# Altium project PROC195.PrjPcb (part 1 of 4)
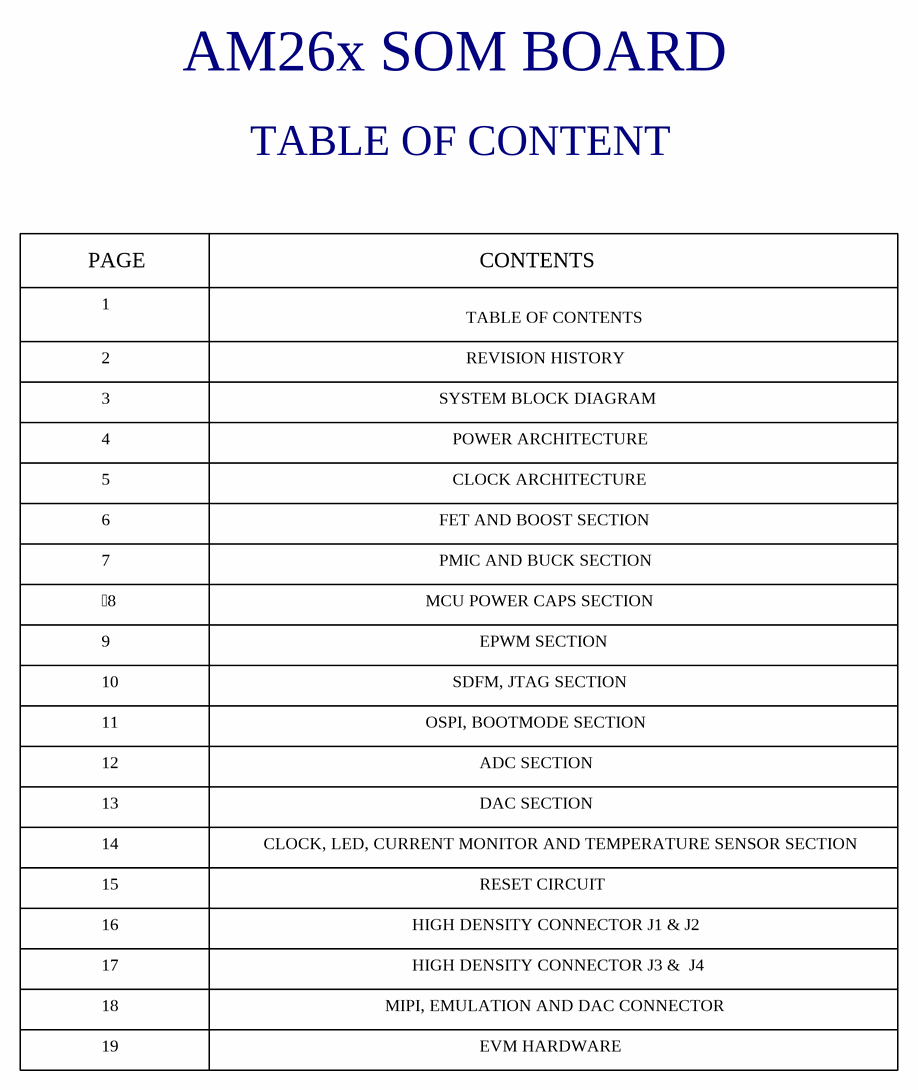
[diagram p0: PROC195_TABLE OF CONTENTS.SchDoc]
TID: N/A; SCH_REV: E1; PRJ_Title: AM26x_SOM; PRJ_Number: PROC195; PRJ_Customer: Public Release; PCB_Rev: E1; EVM_orderable: AM261-SOM-EVM; DrawnBy: Texas Instruments
20 sheets, 559 parts. Net scope: global (net labels, ports and power ports of the same name join across sheets).
Board file: PROC195E1_PCB.PcbDoc
Sheets:
  PROC195_TABLE OF CONTENTS.SchDoc
  PROC195_REVISION_HISTORY.SchDoc
  PROC195_SYSTEM_BLOCK_DIAGRAM.SchDoc
  PROC195_POWER_ARCHITECTURE.SchDoc
  PROC195_CLOCK_ARCHITECTURE.SchDoc
  PROC195_GPIO_TABLE.SchDoc
  PROC195__FET_BOOST_REG.SchDoc
  PROC195_PMIC_BUCK.SchDoc
  PROC195_MCU_POWER_CAPS.SchDoc
  PROC195_EPWM.SchDoc
  PROC195_SDFM, JTAG.SchDoc
  PROC195_OSPI_BOOTMODE.SchDoc
  PROC195_ADC.SchDoc
  PROC195_DAC.SchDoc
  PROC195_CLK_LED_CURRENT_MON_TEMP_CONN.SchDoc
  PROC195_RESET_CIRCUIT.SchDoc
  PROC195_High_density_conn_1_2.SchDoc
  PROC195_High_density_conn3_4.SchDoc
  PROC195_MIPI_Emulation_conn.SchDoc
  PROC195_EVM_Hardware.SchDoc

## Sheet PROC195_TABLE OF CONTENTS.SchDoc
size 431 x 279 mm; Date: Not shown in title block; ApprovedBy: Not shown in title block; CheckedBy: Not shown in title block; Author: Not shown in title block; CompanyName: Not shown in title block; Engineer: Not shown in title block; Organization: Not shown in title block; Address1: Not shown in title block; Address2: Not shown in title block; Address3: Not shown in title block; Address4: Not shown in title block; DocumentNumber: 1; Revision: Use project parameter SCH_Rev; SheetNumber: 1; SheetTotal: 19; PageSetup: Record=PageOptions¦CenterHorizontal=True¦CenterVertical=True¦PrintScale=1.00¦XCorrection=1.00¦YCorrection=1.00¦PrintKind=0¦BorderSize=5000000¦LeftOffset=0¦BottomOffset=0¦Orientation=2¦PaperLength=1000¦PaperWidth=1000¦Scale=100¦PaperSource=15¦PrintQuality=600¦MediaType=1¦DitherType=10¦PaperKind=Letter¦PrintScaleMode=1

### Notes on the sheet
- AM26x SOM BOARD
- TABLE OF CONTENT
- PAGE
- 1
- TABLE OF CONTENTS
- CONTENTS
- 2
- REVISION HISTORY
- 3
- 4
- SYSTEM BLOCK DIAGRAM
- POWER ARCHITECTURE
- 5
- 6
- FET AND BOOST SECTION
- CLOCK ARCHITECTURE
- 7
- PMIC AND BUCK SECTION
- 8
- 9
- MCU POWER CAPS SECTION
- EPWM SECTION
- 10
- 11
- OSPI, BOOTMODE SECTION
- SDFM, JTAG SECTION
- 12
- ADC SECTION
- 13
- 14
- CLOCK, LED, CURRENT MONITOR AND TEMPERATURE SENSOR SECTION
- DAC SECTION
- 15
- 16
- HIGH DENSITY CONNECTOR J1 & J2
- RESET CIRCUIT
- 17
- HIGH DENSITY CONNECTOR J3 &  J4
- 18
- 19
- MIPI, EMULATION AND DAC CONNECTOR
- EVM HARDWARE

## Sheet PROC195_REVISION_HISTORY.SchDoc
size 431 x 279 mm; Date: Not shown in title block; ApprovedBy: Not shown in title block; CheckedBy: Not shown in title block; Author: Not shown in title block; CompanyName: Not shown in title block; Engineer: Not shown in title block; Organization: Not shown in title block; Address1: Not shown in title block; Address2: Not shown in title block; Address3: Not shown in title block; Address4: Not shown in title block; DocumentNumber: 2; Revision: Use project parameter SCH_Rev; SheetNumber: 2; SheetTotal: 20; PageSetup: Record=PageOptions¦CenterHorizontal=True¦CenterVertical=True¦PrintScale=1.00¦XCorrection=1.00¦YCorrection=1.00¦PrintKind=0¦BorderSize=5000000¦LeftOffset=0¦BottomOffset=0¦Orientation=2¦PaperLength=1000¦PaperWidth=1000¦Scale=100¦PaperSource=15¦PrintQuality=600¦MediaType=1¦DitherType=10¦PaperKind=Letter¦PrintScaleMode=1
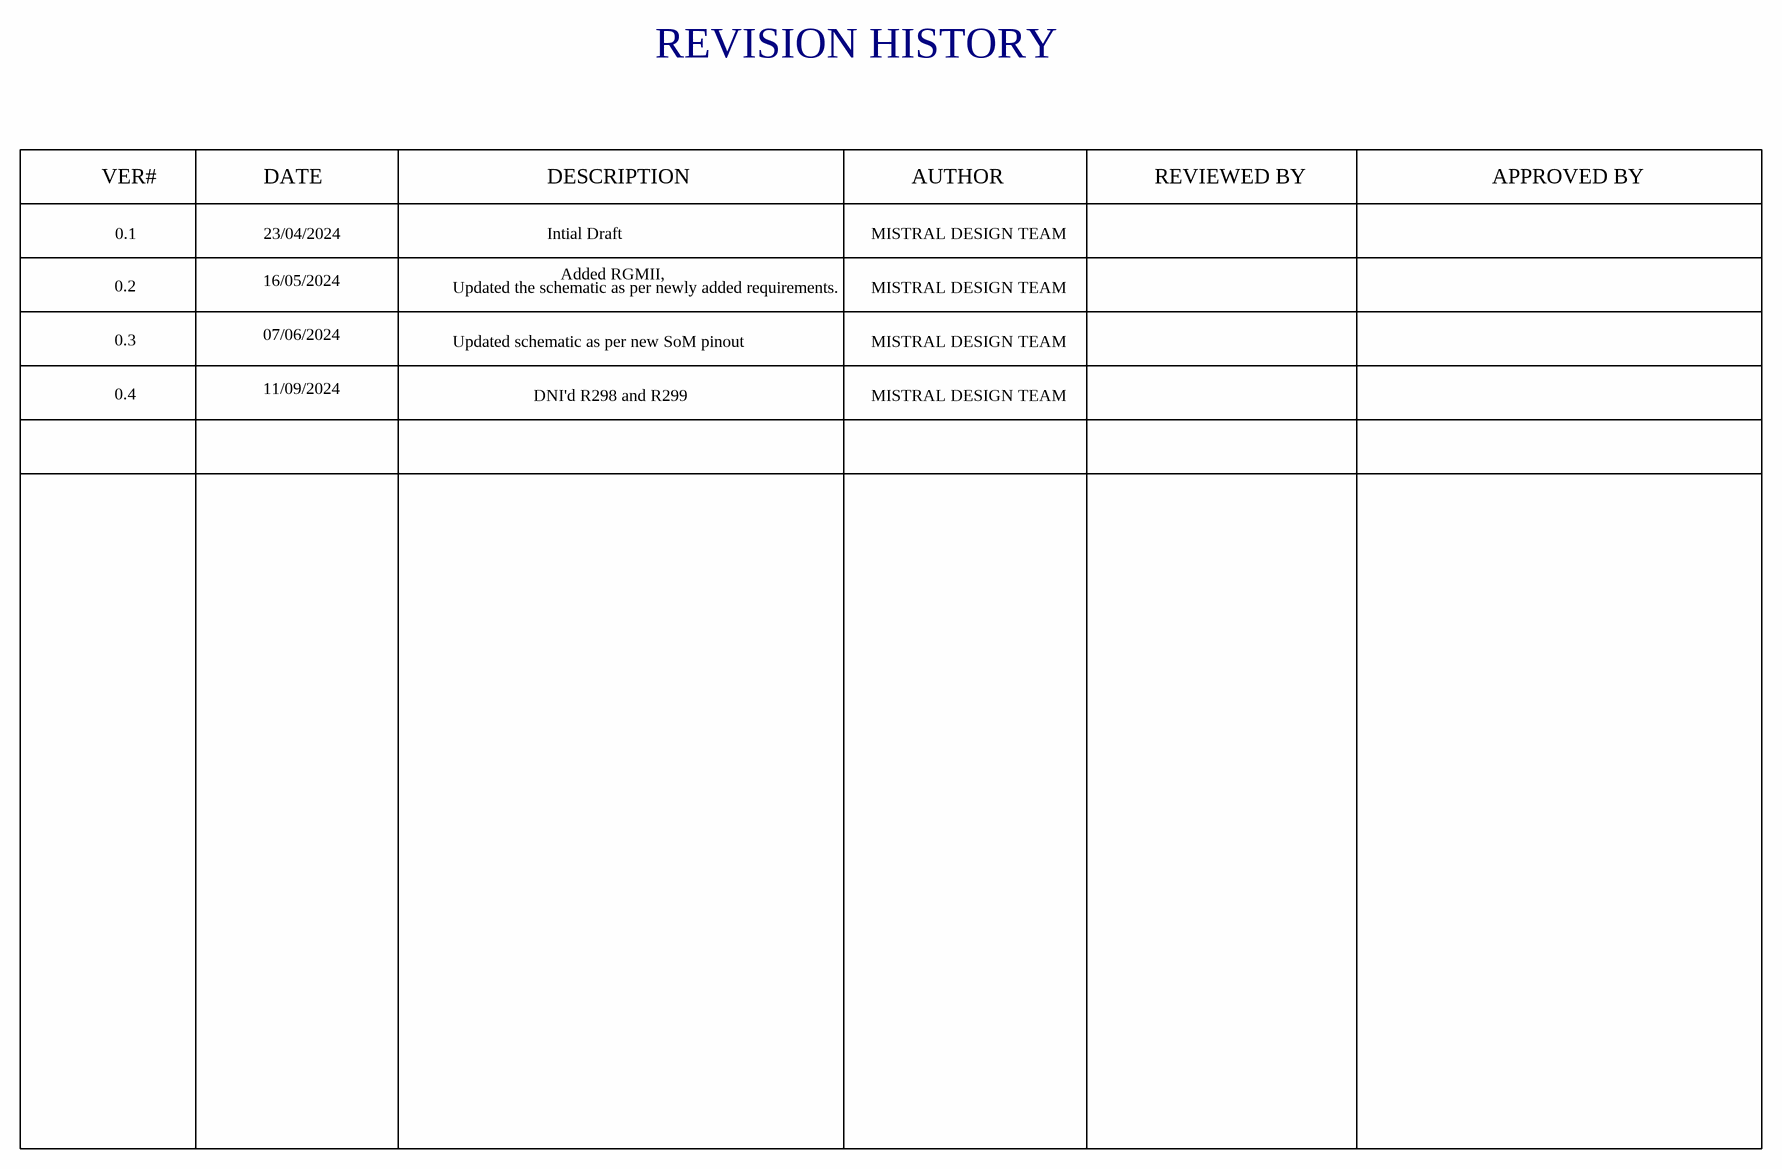
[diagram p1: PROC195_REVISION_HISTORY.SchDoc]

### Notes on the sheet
- REVISION HISTORY
- VER#
- DATE
- DESCRIPTION
- AUTHOR
- REVIEWED BY
- APPROVED BY
- 0.2
- 0.1
- 16/05/2024
- 23/04/2024
- Updated the schematic as per newly added requirements.
- Intial Draft
- Added RGMII,
- MISTRAL DESIGN TEAM
- 0.3
- 07/06/2024
- Updated schematic as per new SoM pinout
- 0.4
- 11/09/2024
- DNI'd R298 and R299

## Sheet PROC195_SYSTEM_BLOCK_DIAGRAM.SchDoc
size 431 x 279 mm; Date: Not shown in title block; ApprovedBy: Not shown in title block; CheckedBy: Not shown in title block; Author: Not shown in title block; CompanyName: Not shown in title block; Engineer: Not shown in title block; Organization: Not shown in title block; Address1: Not shown in title block; Address2: Not shown in title block; Address3: Not shown in title block; Address4: Not shown in title block; DocumentNumber: 3; Revision: Use project parameter SCH_Rev; SheetNumber: 3; SheetTotal: 20; PageSetup: Record=PageOptions¦CenterHorizontal=True¦CenterVertical=True¦PrintScale=1.00¦XCorrection=1.00¦YCorrection=1.00¦PrintKind=0¦BorderSize=5000000¦LeftOffset=0¦BottomOffset=0¦Orientation=2¦PaperLength=1000¦PaperWidth=1000¦Scale=100¦PaperSource=15¦PrintQuality=600¦MediaType=1¦DitherType=10¦PaperKind=Letter¦PrintScaleMode=1
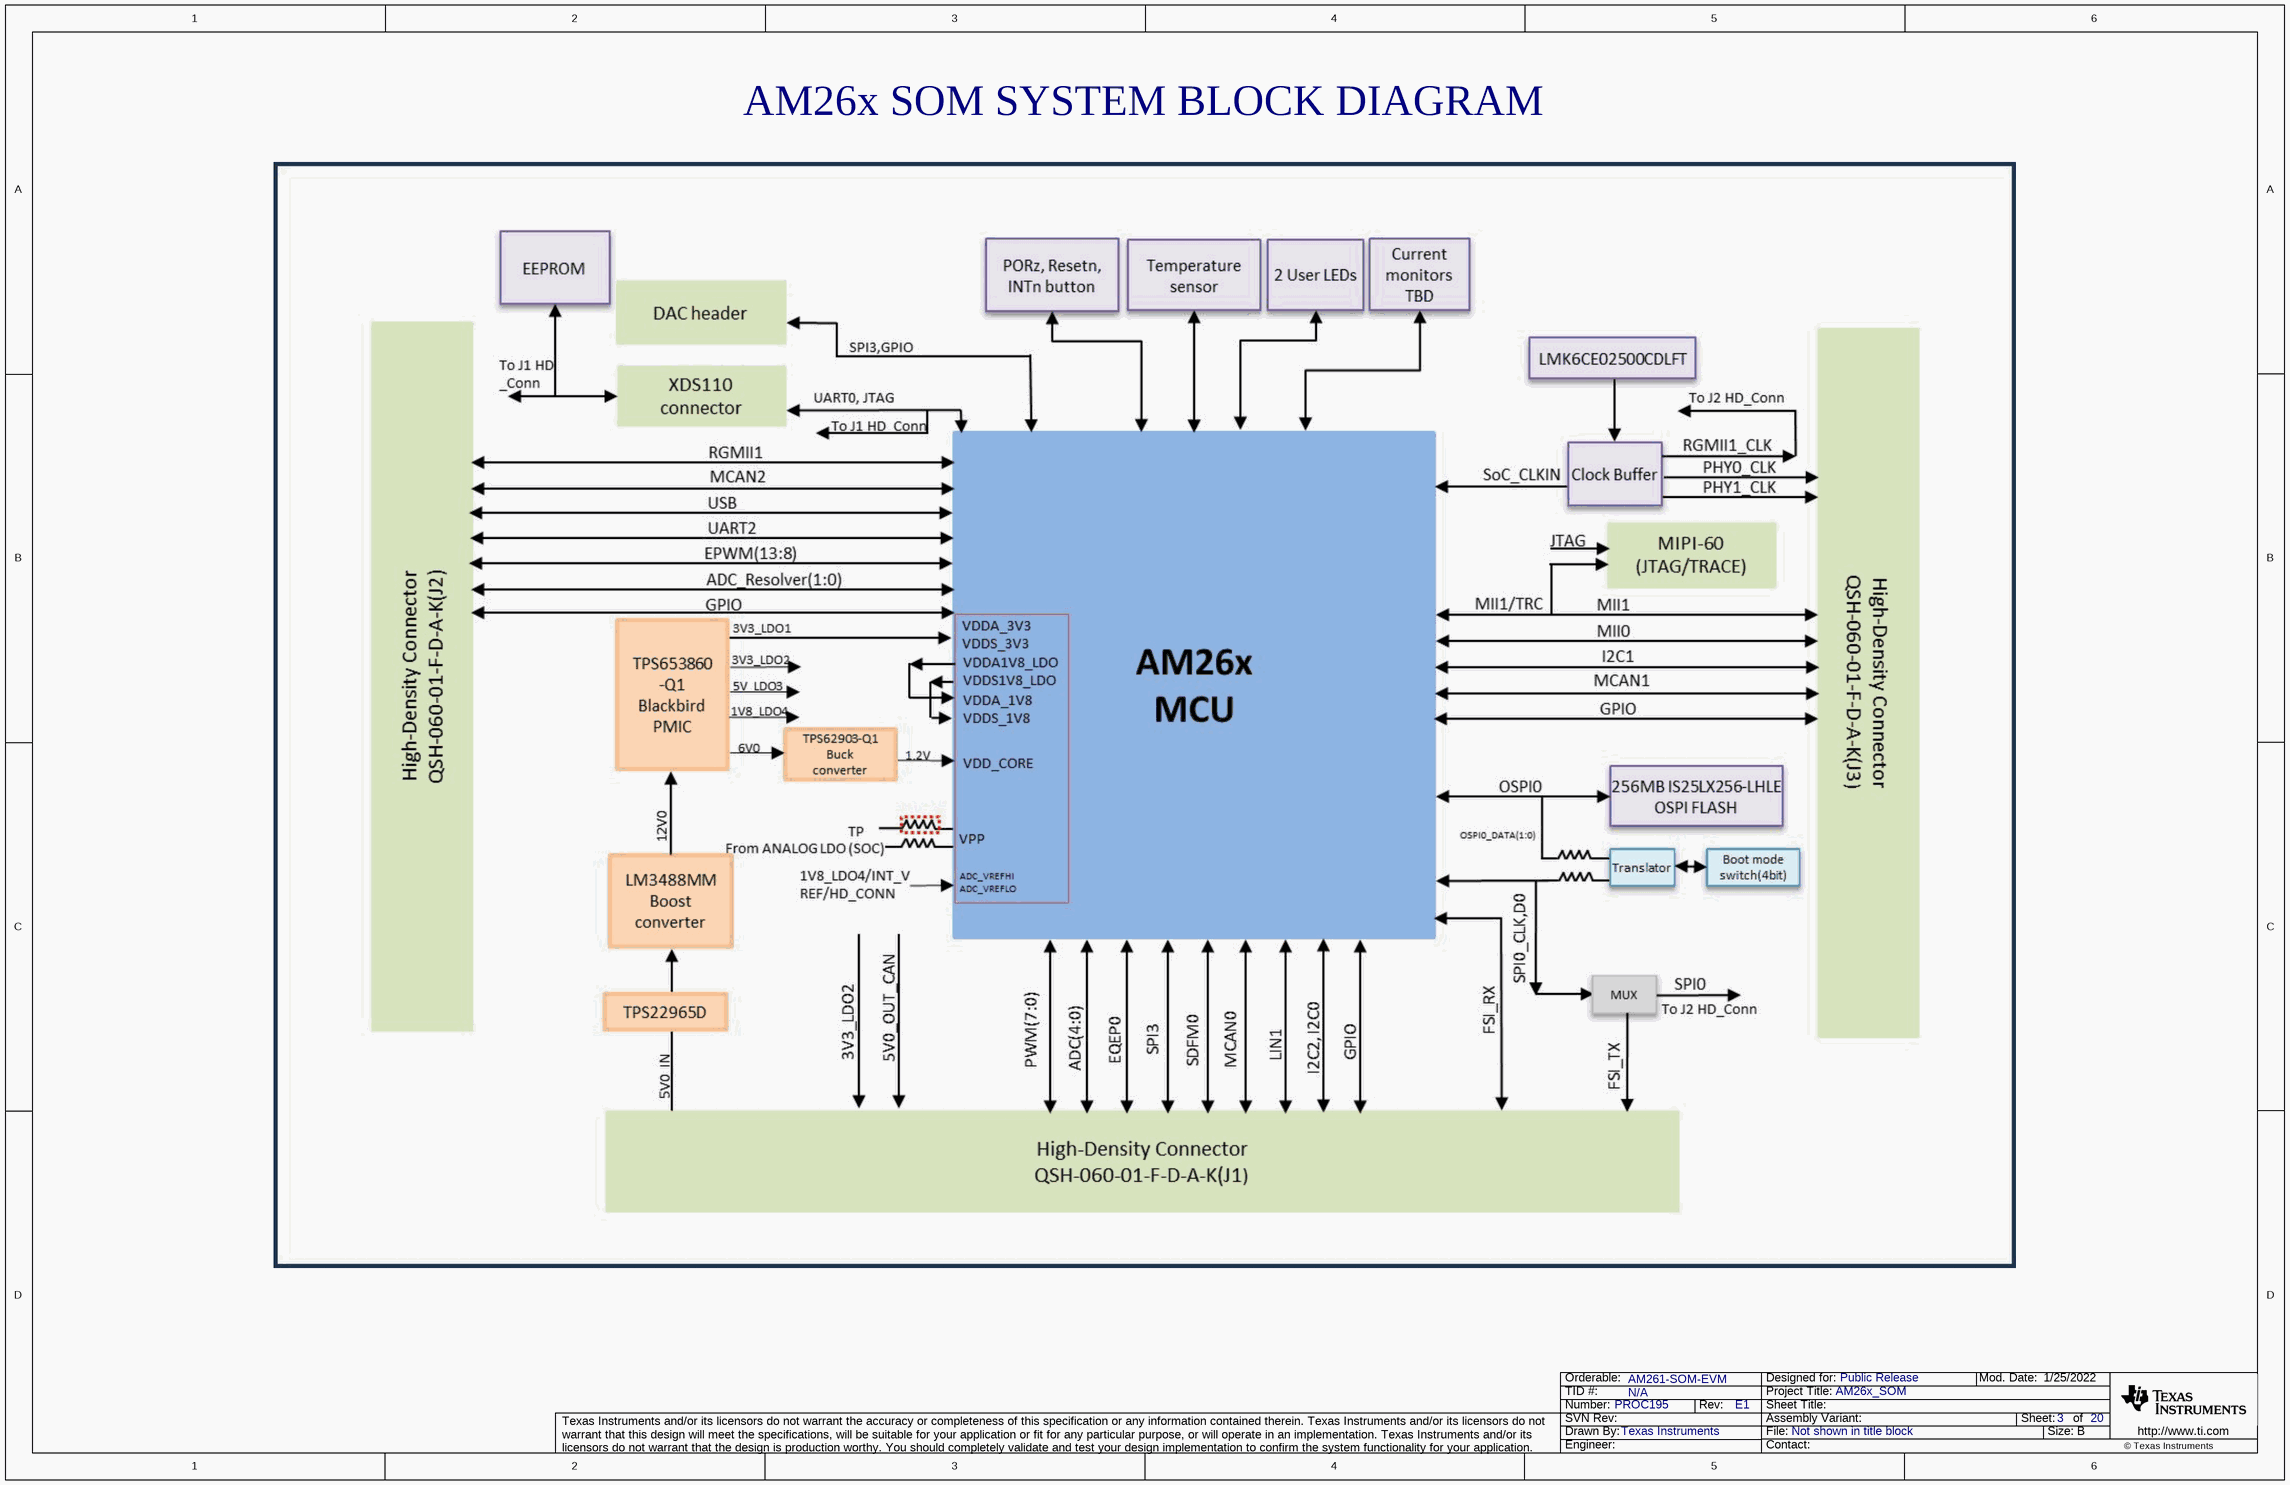
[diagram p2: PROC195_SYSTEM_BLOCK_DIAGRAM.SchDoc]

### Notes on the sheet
- AM26x SOM SYSTEM BLOCK DIAGRAM

## Sheet PROC195_POWER_ARCHITECTURE.SchDoc
size 431 x 279 mm; Date: Not shown in title block; ApprovedBy: Not shown in title block; CheckedBy: Not shown in title block; Author: Not shown in title block; CompanyName: Not shown in title block; Engineer: Not shown in title block; Organization: Not shown in title block; Address1: Not shown in title block; Address2: Not shown in title block; Address3: Not shown in title block; Address4: Not shown in title block; DocumentNumber: 4; Revision: Use project parameter SCH_Rev; SheetNumber: 4; SheetTotal: 19; PageSetup: Record=PageOptions¦CenterHorizontal=True¦CenterVertical=True¦PrintScale=1.00¦XCorrection=1.00¦YCorrection=1.00¦PrintKind=0¦BorderSize=5000000¦LeftOffset=0¦BottomOffset=0¦Orientation=2¦PaperLength=1000¦PaperWidth=1000¦Scale=100¦PaperSource=15¦PrintQuality=600¦MediaType=1¦DitherType=10¦PaperKind=Letter¦PrintScaleMode=1
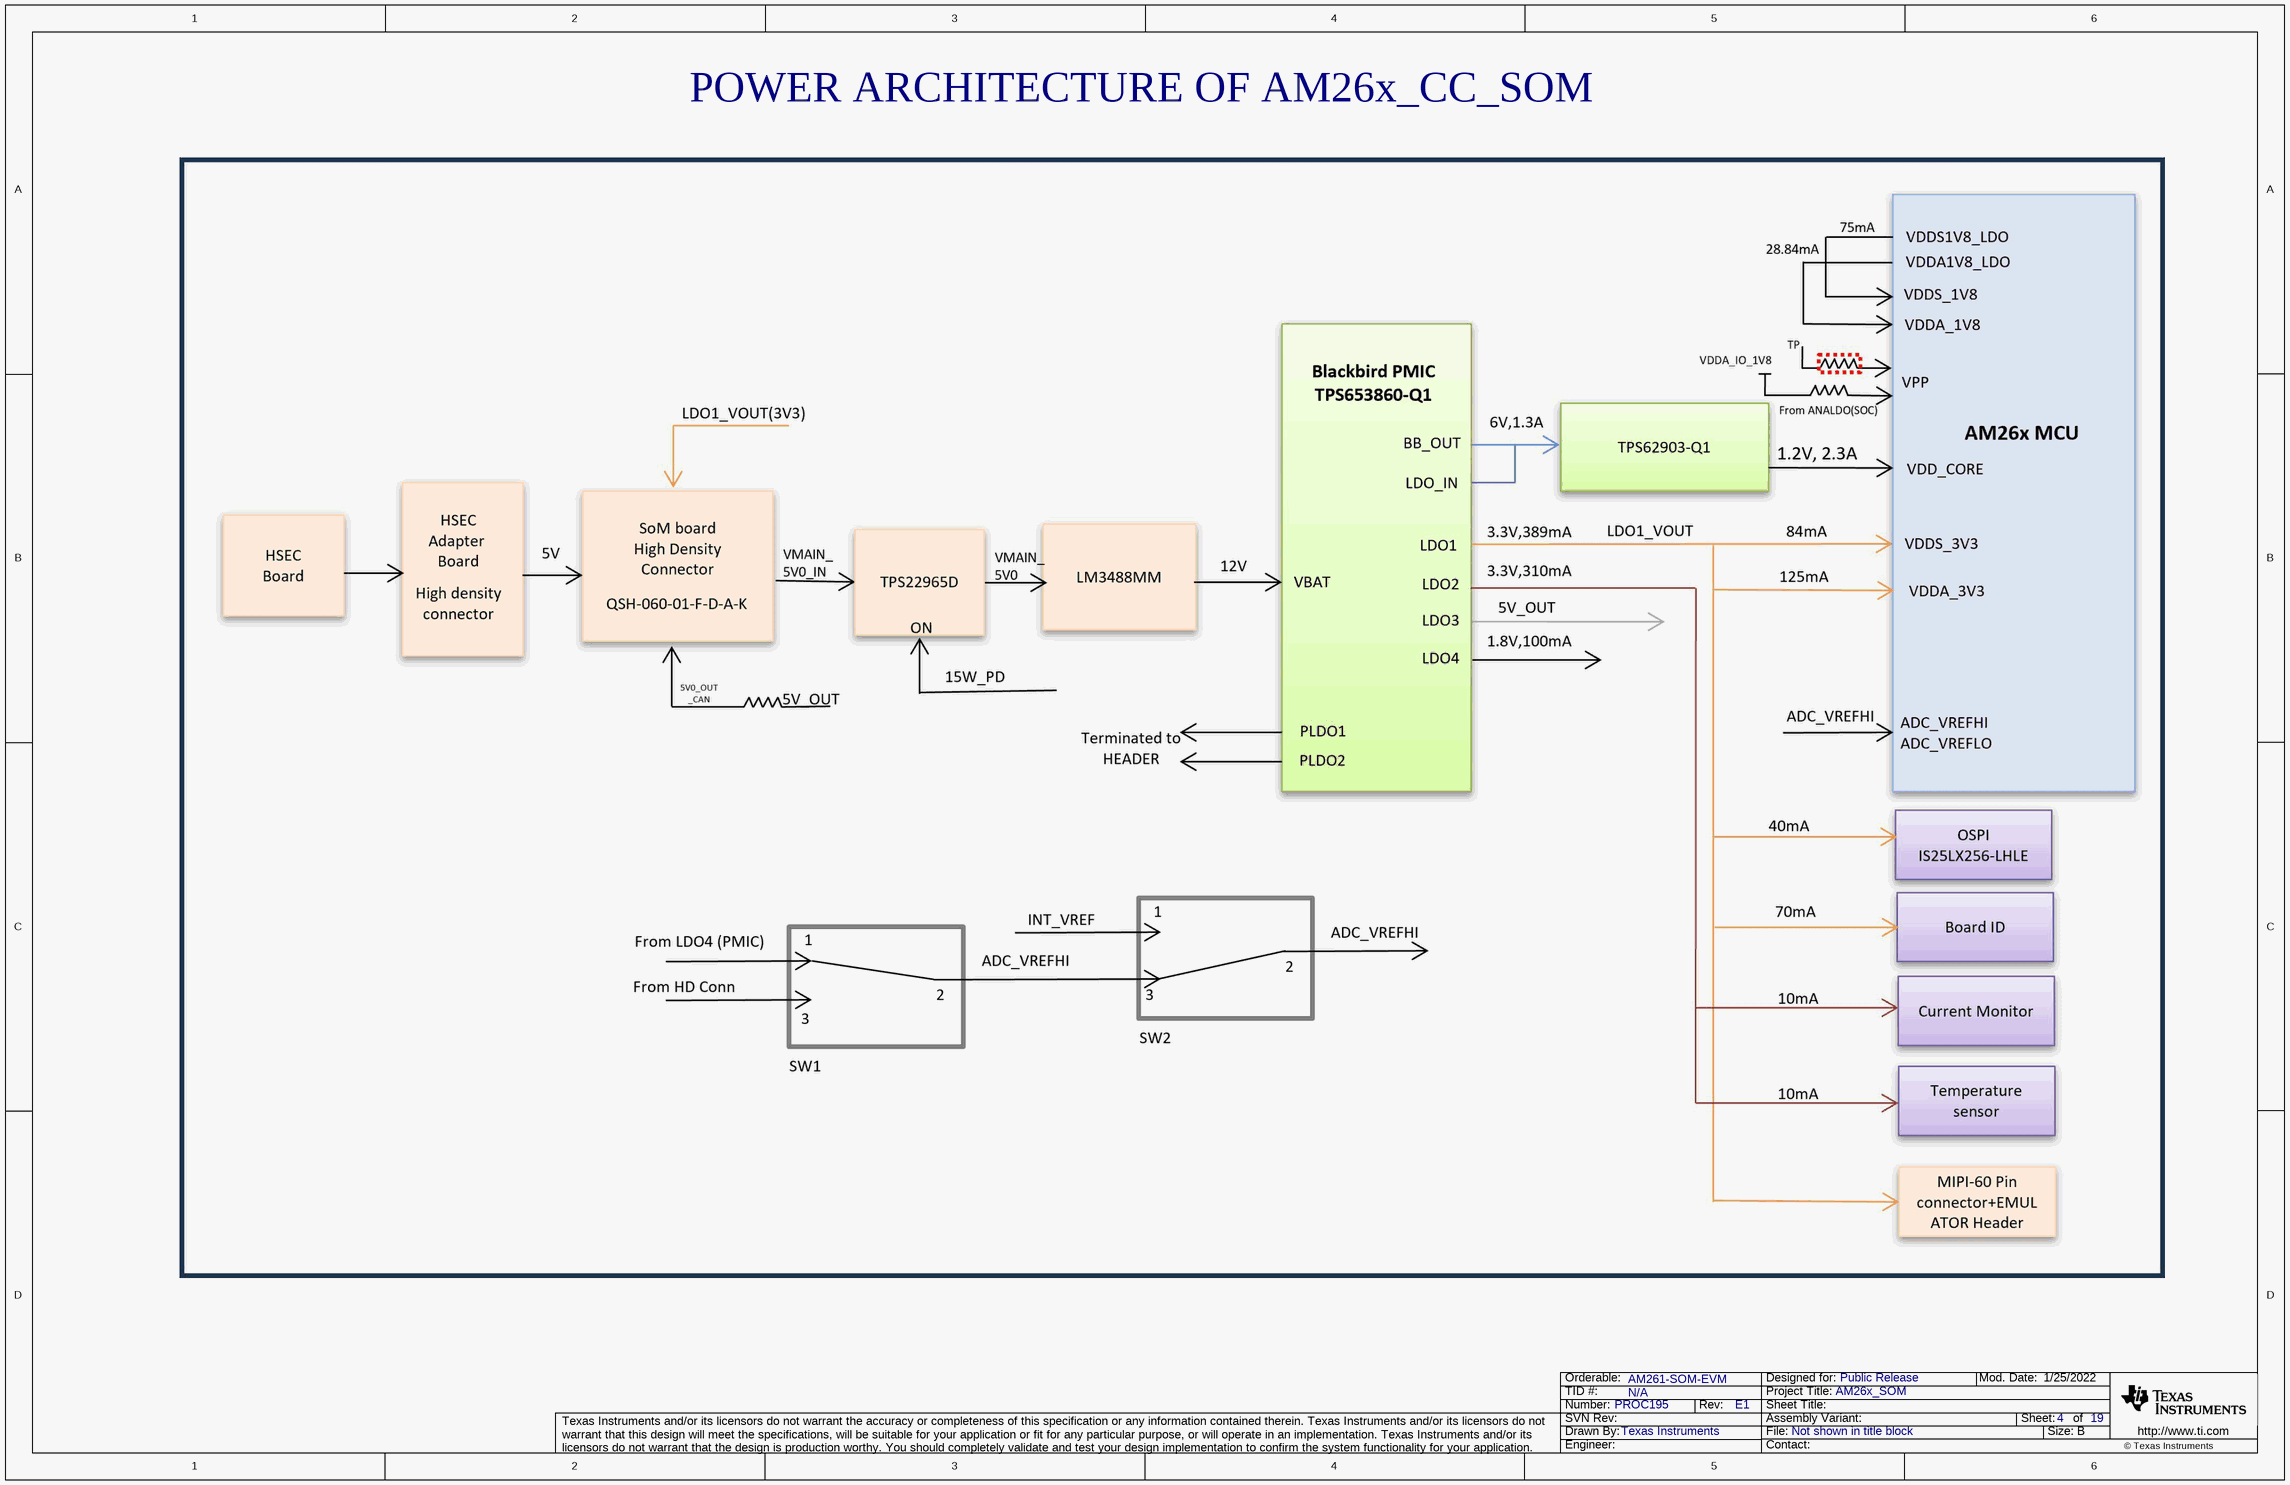
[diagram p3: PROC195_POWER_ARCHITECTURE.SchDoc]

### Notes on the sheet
- POWER ARCHITECTURE OF AM26x_CC_SOM

## Sheet PROC195_CLOCK_ARCHITECTURE.SchDoc
size 431 x 279 mm; Date: Not shown in title block; ApprovedBy: Not shown in title block; CheckedBy: Not shown in title block; Author: Not shown in title block; CompanyName: Not shown in title block; Engineer: Not shown in title block; Organization: Not shown in title block; Address1: Not shown in title block; Address2: Not shown in title block; Address3: Not shown in title block; Address4: Not shown in title block; DocumentNumber: 5; Revision: Use project parameter SCH_Rev; SheetNumber: 5; SheetTotal: 20; PageSetup: Record=PageOptions¦CenterHorizontal=True¦CenterVertical=True¦PrintScale=1.00¦XCorrection=1.00¦YCorrection=1.00¦PrintKind=0¦BorderSize=5000000¦LeftOffset=0¦BottomOffset=0¦Orientation=2¦PaperLength=1000¦PaperWidth=1000¦Scale=100¦PaperSource=15¦PrintQuality=600¦MediaType=1¦DitherType=10¦PaperKind=Letter¦PrintScaleMode=1
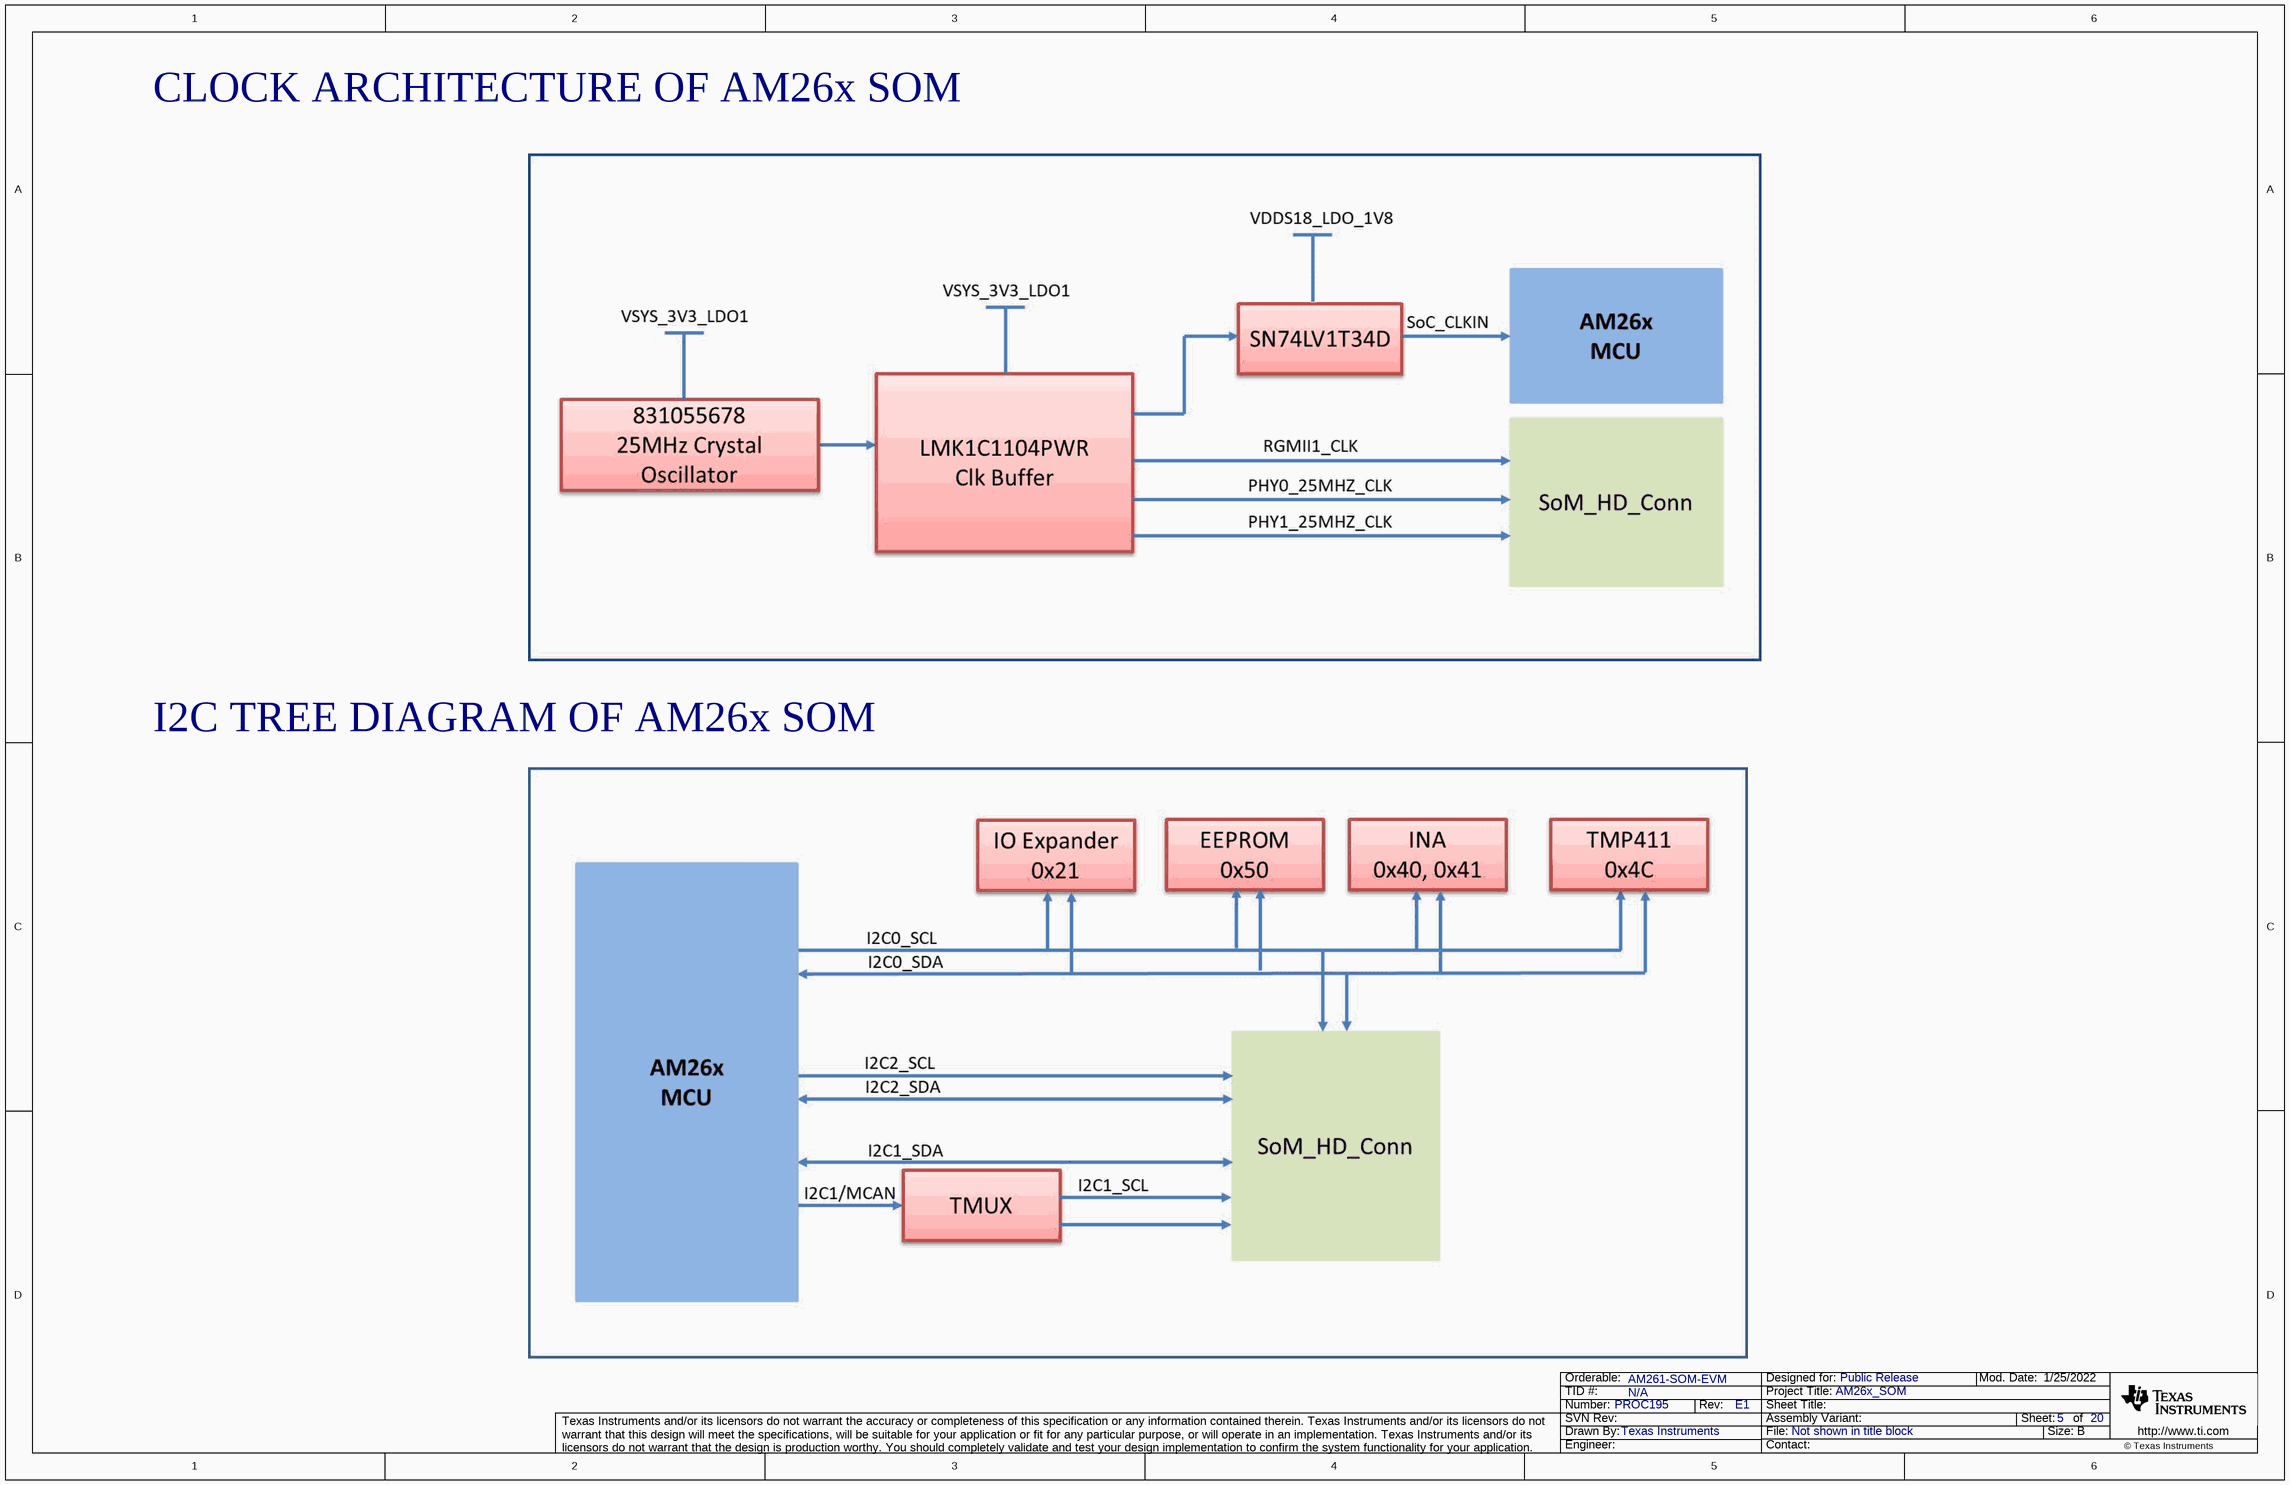
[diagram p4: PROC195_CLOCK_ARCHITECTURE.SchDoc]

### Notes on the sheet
- CLOCK ARCHITECTURE OF AM26x SOM
- I2C TREE DIAGRAM OF AM26x SOM

## Sheet PROC195_GPIO_TABLE.SchDoc
size 431 x 279 mm; Date: Not shown in title block; ApprovedBy: Not shown in title block; CheckedBy: Not shown in title block; Author: Not shown in title block; CompanyName: Not shown in title block; Engineer: Not shown in title block; Organization: Not shown in title block; Address1: Not shown in title block; Address2: Not shown in title block; Address3: Not shown in title block; Address4: Not shown in title block; DocumentNumber: 1; Revision: Use project parameter SCH_Rev; SheetNumber: 6; SheetTotal: 20; PageSetup: Record=PageOptions¦CenterHorizontal=True¦CenterVertical=True¦PrintScale=1.00¦XCorrection=1.00¦YCorrection=1.00¦PrintKind=0¦BorderSize=5000000¦LeftOffset=0¦BottomOffset=0¦Orientation=2¦PaperLength=1000¦PaperWidth=1000¦Scale=100¦PaperSource=15¦PrintQuality=600¦MediaType=1¦DitherType=10¦PaperKind=Letter¦PrintScaleMode=1
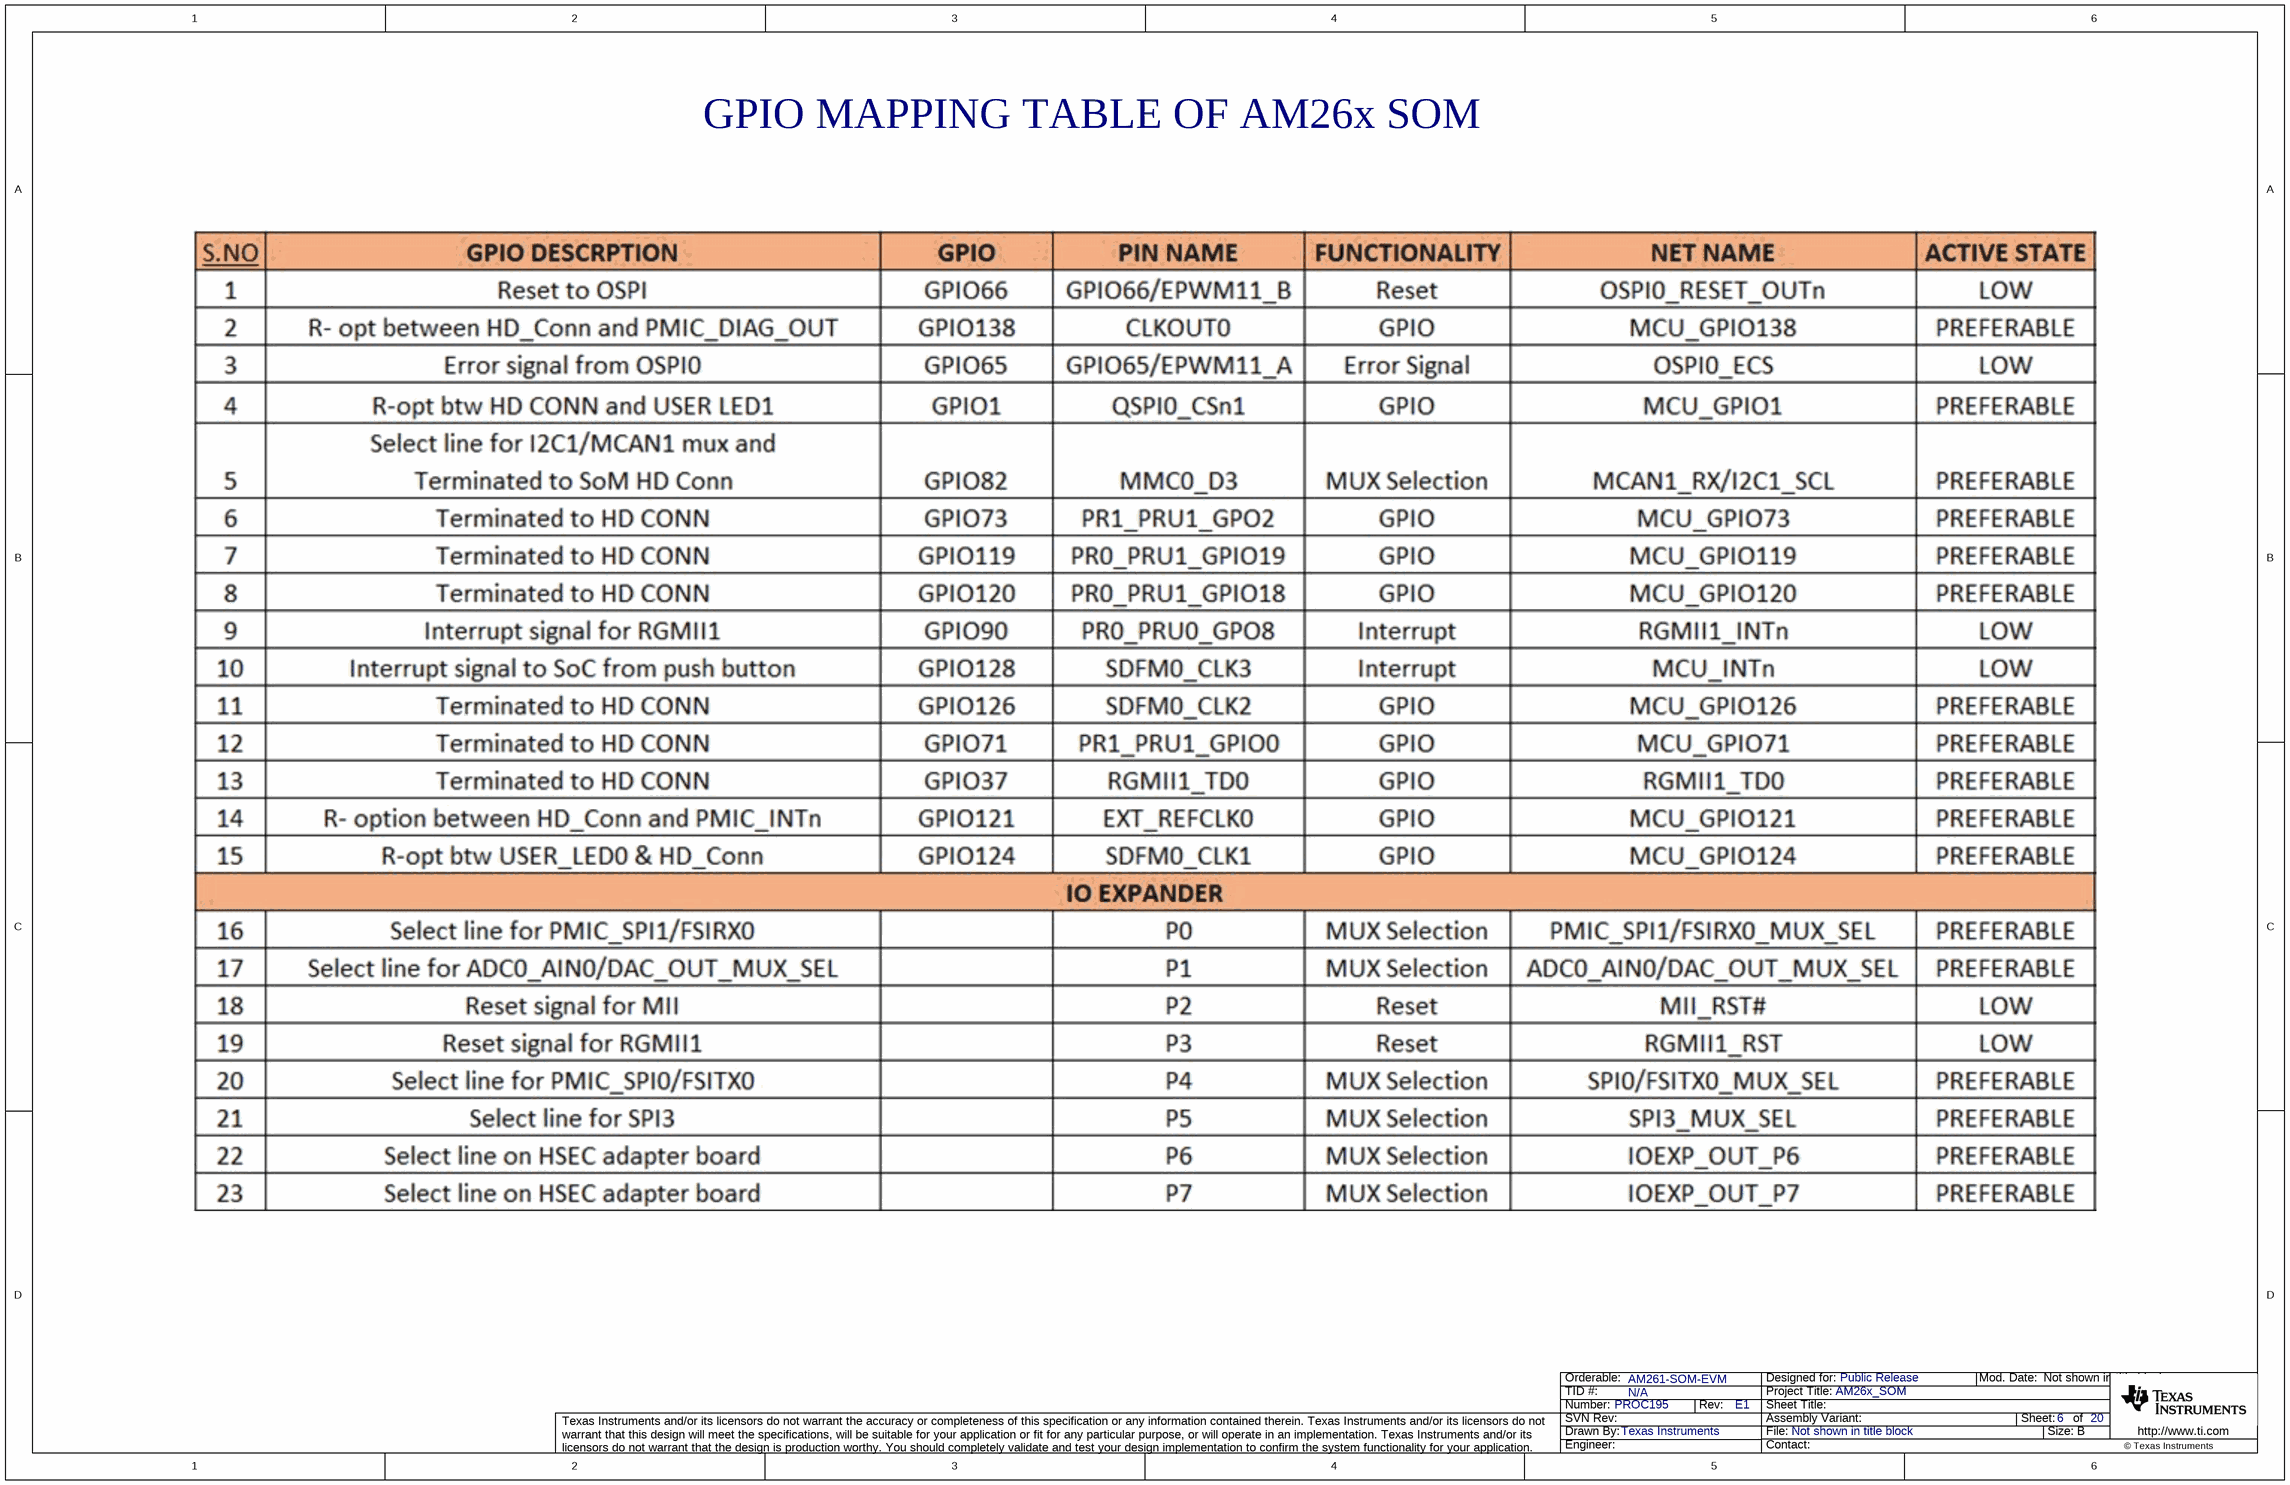
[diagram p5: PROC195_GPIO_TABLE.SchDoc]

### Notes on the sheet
- GPIO MAPPING TABLE OF AM26x SOM

## Sheet PROC195__FET_BOOST_REG.SchDoc
size 431 x 279 mm; Date: Not shown in title block; ApprovedBy: Not shown in title block; CheckedBy: Not shown in title block; Author: Not shown in title block; CompanyName: Not shown in title block; Engineer: Not shown in title block; Organization: Not shown in title block; Address1: Not shown in title block; Address2: Not shown in title block; Address3: Not shown in title block; Address4: Not shown in title block; DocumentNumber: 1; Revision: Use project parameter SCH_Rev; SheetNumber: 7; SheetTotal: 20; PageSetup: Record=PageOptions¦CenterHorizontal=True¦CenterVertical=True¦PrintScale=1.00¦XCorrection=1.00¦YCorrection=1.00¦PrintKind=0¦BorderSize=5000000¦LeftOffset=0¦BottomOffset=0¦Orientation=2¦PaperLength=1000¦PaperWidth=1000¦Scale=100¦PaperSource=15¦PrintQuality=600¦MediaType=1¦DitherType=10¦PaperKind=Letter¦PrintScaleMode=1
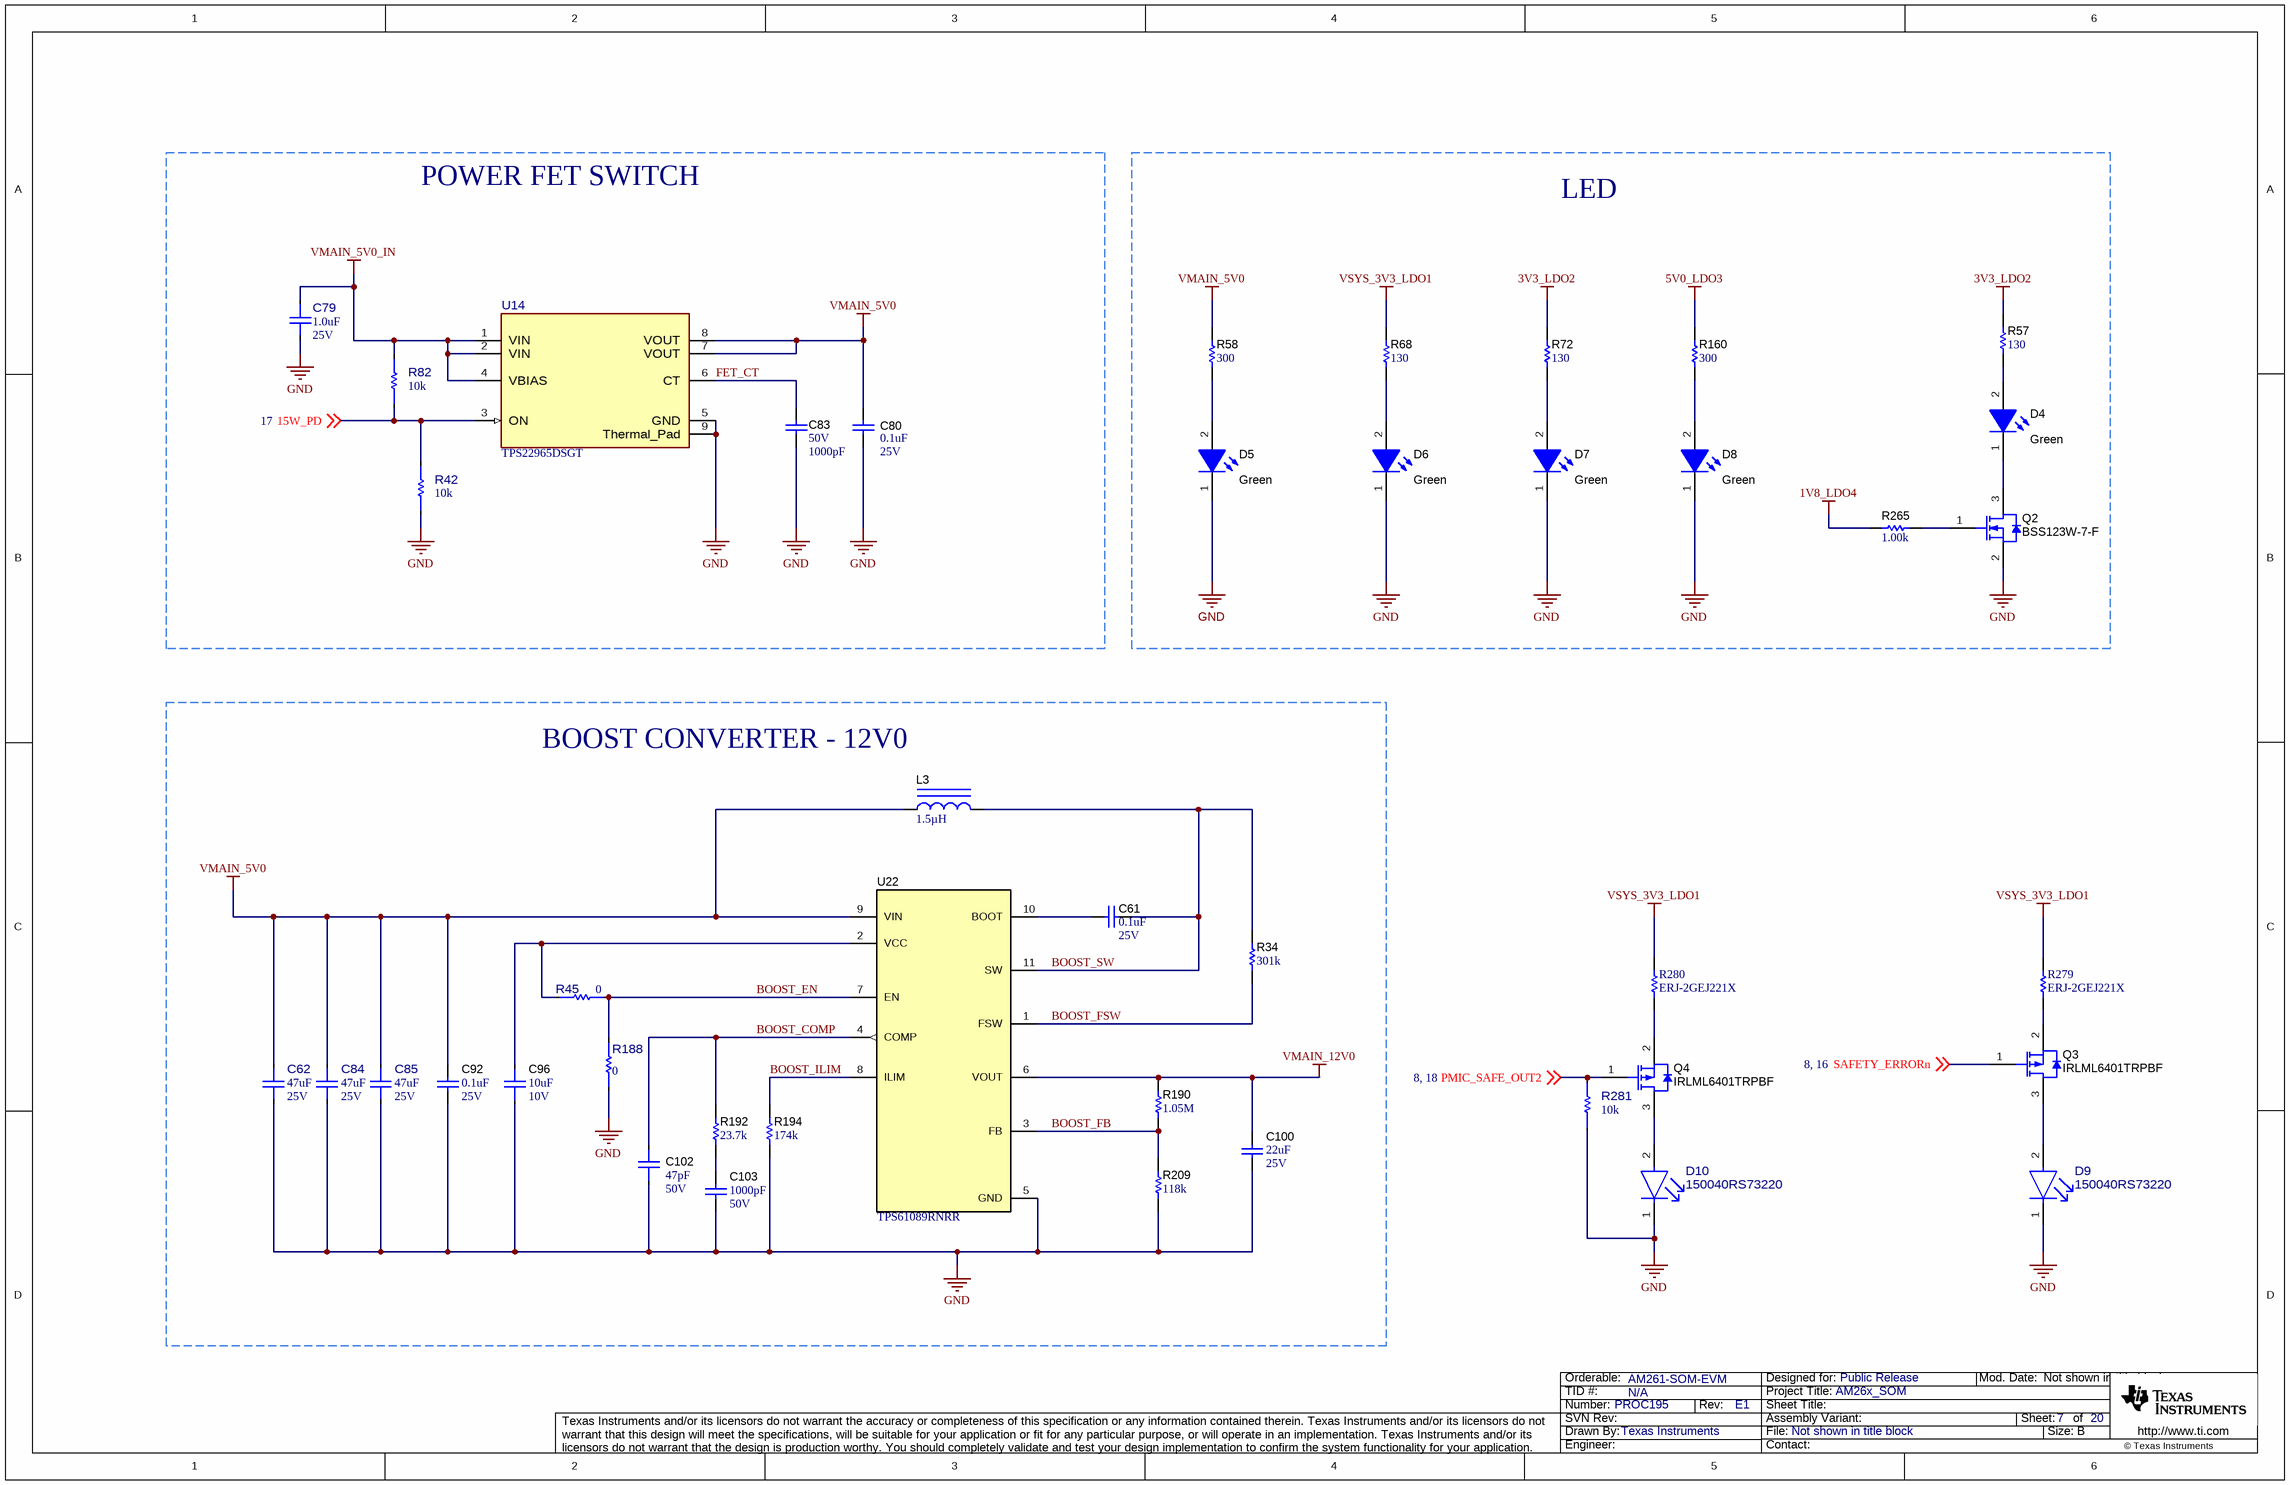
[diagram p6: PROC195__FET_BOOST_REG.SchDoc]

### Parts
C61  VDC_V: 25V  ValueDisplayed: 0.1uF  [0402]  (hidden comment: GRM155R71E104KE14D)
C62  ValueDisplayed: 47uF  VDC_V: 25V  [FP-GRM31CR61E476ME44K_1206-MFG]  (hidden comment: GRM31CR61E476ME44K)
C79  ValueDisplayed: 1.0uF  VDC_V: 25V  [FP-GRM155C81E105KE11D_0402-MFG]  (hidden comment: GRM155C81E105KE11D)
C80  VDC_V: 25V  ValueDisplayed: 0.1uF  [0402]  (hidden comment: GRM155R71E104KE14D)
C83  VDC_V: 50V  ValueDisplayed: 1000pF  [0402]  (hidden comment: GRM1555C1H102JA01D)
C84  ValueDisplayed: 47uF  VDC_V: 25V  [FP-GRM31CR61E476ME44K_1206-MFG]  (hidden comment: GRM31CR61E476ME44K)
C85  ValueDisplayed: 47uF  VDC_V: 25V  [FP-GRM31CR61E476ME44K_1206-MFG]  (hidden comment: GRM31CR61E476ME44K)
C92  VDC_V: 25V  ValueDisplayed: 0.1uF  [0402]  (hidden comment: GRM155R71E104KE14D)
C96  VDC_V: 10V  ValueDisplayed: 10uF  [FP-GRM155R61A106ME18D_0402-MFG]  (hidden comment: GRM155R61A106ME18D)
C100  VDC_V: 25V  ValueDisplayed: 22uF  [0805_HV]  (hidden comment: GRM21BR61E226ME44L)
C102  ValueDisplayed: 47pF  VDC_V: 50V  [FP-GJM1555C1H470JB01D_0402-MFG]  (hidden comment: GJM1555C1H470JB01D)
C103  VDC_V: 50V  ValueDisplayed: 1000pF  [0402]  (hidden comment: GRM1555C1H102JA01D)
D4  value Green  [WL-SMCW_GREEN]  (hidden comment: 150060VS75000)
D5  value Green  [WL-SMCW_GREEN]  (hidden comment: 150060VS75000)
D6  value Green  [WL-SMCW_GREEN]  (hidden comment: 150060VS75000)
D7  value Green  [WL-SMCW_GREEN]  (hidden comment: 150060VS75000)
D8  value Green  [WL-SMCW_GREEN]  (hidden comment: 150060VS75000)
D9  150040RS73220  [FP-150040RS73220_0402-MFG]
D10  150040RS73220  [FP-150040RS73220_0402-MFG]
L3  ValueDisplayed: 1.5µH  [DFE252012P]  (hidden comment: DFE252012P-1R5M=P2)
Q2  BSS123W-7-F  [SOT-323]
Q3  IRLML6401TRPBF  [SOT-23]
Q4  IRLML6401TRPBF  [SOT-23]
R34  ValueDisplayed: 301k  [0402]  (hidden comment: CRCW0402301KFKED)
R42  value 10k  [FP-RC0402JR-0710KL_0402-MFG]  (hidden comment: RC0402JR-0710KL)
R45  value 0  [FP-ERJ-2GE0R00X_0402-MFG]  (hidden comment: ERJ-2GE0R00X)
R57  ValueDisplayed: 130  [0402]  (hidden comment: CRCW0402130RFKED)
R58  ValueDisplayed: 300  [0201]  (hidden comment: RC0201JR-7D300RL)
R68  ValueDisplayed: 130  [0402]  (hidden comment: CRCW0402130RFKED)
R72  ValueDisplayed: 130  [0402]  (hidden comment: CRCW0402130RFKED)
R82  value 10k  [FP-RC0402JR-0710KL_0402-MFG]  (hidden comment: RC0402JR-0710KL)
R160  ValueDisplayed: 300  [0201]  (hidden comment: RC0201JR-7D300RL)
R188  value 0  [FP-ERJ-2GE0R00X_0402-MFG]  (hidden comment: ERJ-2GE0R00X)
R190  ValueDisplayed: 1.05M  [0402]  (hidden comment: CRCW04021M05FKED)
R192  ValueDisplayed: 23.7k  [0402]  (hidden comment: CRCW040223K7FKED)
R194  ValueDisplayed: 174k  [0402]  (hidden comment: CRCW0402174KFKED)
R209  ValueDisplayed: 118k  [0402]  (hidden comment: CRCW0402118KFKED)
R265  ValueDisplayed: 1.00k  [0402]  (hidden comment: ERJ-2RKF1001X)
R279  ERJ-2GEJ221X  [RESC1005X40X25LL05T05]
R280  ERJ-2GEJ221X  [RESC1005X40X25LL05T05]
R281  value 10k  [FP-RC0402JR-0710KL_0402-MFG]  (hidden comment: RC0402JR-0710KL)
U14  TPS22965DSGT  [DSG0008A-MFG]
U22  TPS61089RNRR  [RNR0011A]

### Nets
1V8_LDO4: R265.1
3V3_LDO2: R57.1 R72.1
5V0_LDO3: R160.1
GND: C62.2 C79.2 C80.2 C83.1 C84.2 C85.2 C92.2 C96.1 C100.1 C102.1 C103.1 D5.1(K) D6.1(K) D7.1(K) D8.1(K) D9.1(CATHODE) D10.1(CATHODE) Q2.2(S) R42.1 R188.1 R194.1 R209.1 R281.1 U14.5(GND) U14.9(Thermal_Pad) U22.5(GND)
VMAIN_5V0: C62.1 C80.1 C84.1 C85.1 C92.1 L3.1 R58.1 U14.7(VOUT) U14.8(VOUT) U22.9(VIN)
VMAIN_5V0_IN: C79.1 R82.2 U14.1(VIN) U14.2(VIN) U14.4(VBIAS)
VMAIN_12V0: C100.2 R190.2 U22.6(VOUT)
VSYS_3V3_LDO1: R68.1 R279.2 R280.2
15W_PD: R42.2 R82.1 U14.3(ON) ; off-sheet 15W_PD
BOOST_COMP: C102.2 R192.2 U22.4(COMP)
BOOST_EN: R45.2 R188.2 U22.7(EN)
BOOST_FB: R190.1 R209.2 U22.3(FB)
BOOST_FSW: R34.1 U22.1(FSW)
BOOST_ILIM: R194.2 U22.8(ILIM)
BOOST_SW: C61.1 L3.2 R34.2 U22.11(SW)
FET_CT: C83.2 U14.6(CT)
PMIC_SAFE_OUT2: Q4.1(G) R281.2 ; off-sheet PMIC_SAFE_OUT2
SAFETY_ERRORn: Q3.1(G) ; off-sheet SAFETY_ERRORn
NetC61_2: C61.2 U22.10(BOOT)
NetC96_2: C96.2 R45.1 U22.2(VCC)
NetC103_2: C103.2 R192.1
NetD4_1: D4.1(K) Q2.3(D)
NetD4_2: D4.2(A) R57.2
NetD5_2: D5.2(A) R58.2
NetD6_2: D6.2(A) R68.2
NetD7_2: D7.2(A) R72.2
NetD8_2: D8.2(A) R160.2
NetD9_2: D9.2(ANODE) Q3.3(D)
NetD10_2: D10.2(ANODE) Q4.3(D)
NetQ2_1: Q2.1(G) R265.2
NetQ3_2: Q3.2(S) R279.1
NetQ4_2: Q4.2(S) R280.1

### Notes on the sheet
- POWER FET SWITCH
- LED
- BOOST CONVERTER - 12V0

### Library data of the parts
C61 C80 C92 = CMP-0006659-2: CAP, CERM, 0.1 uF, 25 V, +/- 10%, X7R, 0402; Manufacturer: MuRata; TaMin_C: -55°C; Polarized: N; SizeAreaWB_mm2: 3; Value1: Unknown; U/M: EA; Value: 0.1uF; TaMax_C: 125°C; SizeZ_mm: 0.6; SizeX_mm: 1; SizeY_mm: 0.5; Cap_F: 100nF; AEC Category: Q200
C62 C84 C85 = CMP-0122098-1: Cap Ceramic Monolithic 47uF 25VDC 20% SMD Emboss T/R; Manufacturer: Murata; AEC Qualified: No; Cap_F: 47µF; SizeZ_mm: 1.8mm; TempCo: 15%; Temperature Characteristic: X5R; Value: 47µF
C79 = CMP-0121658-2: Chip Multilayer Ceramic Capacitors for General Purpose, 0402, 1.0uF, X6S, 22%, 10%, 25V; Manufacturer: Murata; AEC Qualified: No; Cap_F: 1µF; SizeZ_mm: 0.6mm; Value: 1µF
C83 C103 = CMP-0006412-2: CAP, CERM, 1000 pF, 50 V, +/- 5%, C0G/NP0, 0402; Manufacturer: MuRata; TaMin_C: -55°C; Polarized: N; SizeAreaWB_mm2: 3; Value1: Unknown; U/M: EA; Value: 1000pF; TaMax_C: 125°C; SizeZ_mm: 0.6; SizeX_mm: 1; SizeY_mm: 0.5; Cap_F: 1nF; AEC Category: Q200
C96 = CMP-0120207-1: 10 µF ±20% 10V Ceramic Capacitor X5R 0402 (1005 Metric); Manufacturer: Murata; Cap_F: 10µF; TempCo: 15%; SizeZ_mm: 0.7mm; Value: 10µF; AEC Qualified: No
C100 = CMP-0008305-2: CAP, CERM, 22 uF, 25 V, +/- 20%, X5R, 0805; Manufacturer: MuRata; TaMin_C: -55°C; Polarized: N; SizeAreaWB_mm2: 6.75; Value1: Unknown; U/M: EA; Value: 22uF; TaMax_C: 85°C; SizeZ_mm: 1.45; SizeX_mm: 2; SizeY_mm: 1.25; Cap_Case: 0805; SizeArea_mm2: 2.5; Cap_F: 22µF; AEC Category: Q200
C102 = CMP-0120205-1: Multi-Layer Ceramic Capacitor 47pF C0G  ±5% 0402 Paper T/R; Manufacturer: Murata; AEC Qualified: No; SizeZ_mm: 0.55mm; TempCo: 30ppm/°C
D4-D8 = CMP-0002894-2: LED, Green, SMD; Manufacturer: Wurth Elektronik; Type: AlInGaP; Value2: 2V; Io_A: 20mA; Value1: W
D9 D10 = CMP-0122246-1: Red 624nm LED Indication - Discrete 2V 0402 (1005 Metric); Manufacturer: Wurth; Angle: 120°; LambdaP: 632nm; Power_TotalModule: 48mW; SizeZ_mm: 0.35mm; Tjmax_C: 115°C; Vr_V: 5V; AEC Qualified: No; Forward Current: 20mA; Led Orientation: Top View; Luminous Intensity: 110mcd
L3 = CMP-0082609-1: Inductor, Shielded, Metal Composite, 1.5 µH, 2.6 A, 0.06 ohm, SMD; Manufacturer: MuRata; Isat: 3.5A @ 30% inductance drop; Irms: 2.6A @ 40C rise; SizeAreaWB_mm2: 10.5; DCR_ohm: 0.06; Value: 1.5uH; Imax_A: 2.6A; SizeZ_mm: 1.2; SizeX_mm: 2.5; SizeY_mm: 2; SizeArea_mm2: 5; AEC Qualified: N; AEC Category: Q200
Q2 = CMP-0000948-2: MOSFET, N-CH, 100 V, 0.17 A, SOT-323; Alternate Manufacturer: None; Manufacturer: Diodes Inc.; SizeZ_mm: 1.1; ChType: N; Value1: 1; VdsMax_V: 100V; SizeX_mm: 2.2; Vgs_V: 20V; Value: 100V; Rdson45_ohm: 10; SizeArea_mm2: 4.84; AEC Category: Q101; IdsMax_A: 1.7dA; SizeAreaWB_mm2: 10.24; U/M: EA
Q3 Q4 = CMP-0078819-2: MOSFET, P-CH, -12 V, -4.3 A, SOT-23; Alternate Manufacturer: None; Manufacturer: Infineon Technologies; SizeY_mm: 3; ChMode: Enhancement; SizeX_mm: 2.5; QgTyp_nC: 10; ChType: P; AEC Qualified: N; Value2: 10 nC; SizeZ_mm: 1.1; Green_Lifecycle: Active; Vgs_V: -8V; SizeArea_mm2: 7.5; Value: -12V; IdsMax_A: -4.3A; SizeAreaWB_mm2: 14; AEC Category: Q101; Value1: 0.05 ohm; Rdson45_ohm: 0.05; Green_REACh: Passed
R34 = CMP-0026280-2: RES, 301 k, 1%, 0.063 W, AEC-Q200 Grade 0, 0402; Manufacturer: Vishay-Dale; Power_W: 63mW; TempCo: 100 ppm/C; Value: 301k; EIA_Code: E96; SizeX_mm: 1; SizeY_mm: 0.5; SizeZ_mm: 0.6; Value2: 0.063W; AEC Qualified: Y; VDC_V: 50V; AEC Category: Q200; AEC Grade: 0
R42 R82 R281 = CMP-0094798-1: Res Thick Film 0402 10K Ohm 5% 0.063W(1/16W) ±100ppm/C Pad SMD T/R; Manufacturer: YAGEO; Power_W: 63mW; TempCo: 100ppm/°C; SizeZ_mm: 0.4mm; AEC Qualified: No; VDC_V: 50V; Category Cd01000Bfc2916C6: Single Components; Category 5C6A91606D4187Ad: Resistors; Category 7542B8484461Ae85: Passive Components
R45 R188 = CMP-0002710-1: 0 Ohms Jumper Chip Resistor 0402 (1005 Metric) Automotive AEC-Q200 Thick Film; Manufacturer: Panasonic; AEC Grade: Grade 0; AEC Qualified: Yes; SizeZ_mm: 0.4mm; Power: 100mW
R57 R68 R72 = CMP-0025998-3: RES, 130, 1%, 0.063 W, AEC-Q200 Grade 0, 0402; Manufacturer: Vishay-Dale; Power_W: 63mW; TempCo: 100 ppm/C; Value_Code: 130R; Value: 130; EIA_Code: E96; SizeX_mm: 1; SizeY_mm: 0.5; SizeZ_mm: 0.6; Value2: 0.063W; AEC Qualified: Y; VDC_V: 50V; AEC Category: Q200; AEC Grade: 0
R58 R160 = CMP-0027222-1: RES, 300, 5%, 0.05 W, 0201; Manufacturer: Yageo America; Power_W: 50mW; TempCo: 200 ppm/C; Value_Code: 300R; U/M: EA; Value: 300; EIA_Code: E24; SizeX_mm: 0.6; SizeY_mm: 0.3; SizeZ_mm: 0.26; Value2: 0.05W; SizeArea_mm2: 0.18; AEC Qualified: N; VDC_V: 25V; AEC Category: Q200
R190 = CMP-0026102-2: RES, 1.05 M, 1%, 0.063 W, AEC-Q200 Grade 0, 0402; Manufacturer: Vishay-Dale; Power_W: 63mW; TempCo: 100 ppm/C; Value_Code: 1M05; Value: 1.05Meg; EIA_Code: E96; SizeX_mm: 1; SizeY_mm: 0.5; SizeZ_mm: 0.6; Value2: 0.063W; AEC Qualified: Y; VDC_V: 50V; AEC Category: Q200; AEC Grade: 0
R192 = CMP-0026187-2: RES, 23.7 k, 1%, 0.063 W, AEC-Q200 Grade 0, 0402; Manufacturer: Vishay-Dale; Power_W: 63mW; TempCo: 100 ppm/C; Value_Code: 23k7; Value: 23.7k; EIA_Code: E96; SizeX_mm: 1; SizeY_mm: 0.5; SizeZ_mm: 0.6; Value2: 0.063W; AEC Qualified: Y; VDC_V: 50V; AEC Category: Q200; AEC Grade: 0
R194 = CMP-0026046-3: RES, 174 k, 1%, 0.063 W, AEC-Q200 Grade 0, 0402; Manufacturer: Vishay-Dale; Power_W: 63mW; TempCo: 100 ppm/C; Value: 174k; EIA_Code: E96; SizeX_mm: 1; SizeY_mm: 0.5; SizeZ_mm: 0.6; Value2: 0.063W; AEC Qualified: Y; VDC_V: 50V; AEC Category: Q200; AEC Grade: 0
R209 = CMP-0025973-3: RES, 118 k, 1%, 0.063 W, AEC-Q200 Grade 0, 0402; Manufacturer: Vishay-Dale; Power_W: 63mW; TempCo: 100 ppm/C; Value: 118k; EIA_Code: E96; SizeX_mm: 1; SizeY_mm: 0.5; SizeZ_mm: 0.6; Value2: 0.063W; AEC Qualified: Y; VDC_V: 50V; AEC Category: Q200; AEC Grade: 0
R265 = CMP-0026657-1: RES, 1.00 k, 1%, 0.1 W, 0402; Manufacturer: Panasonic; Power_W: 100mW; TempCo: 100 ppm/C; Value_Code: 1k00; U/M: EA; Value: 1.00k; EIA_Code: E96; Res_ohm: 1k; SizeX_mm: 1; SizeY_mm: 0.5; SizeZ_mm: 0.6; Value2: 0.1W; VDC_V: 50V; AEC Category: Q200
R279 R280 = CMP-2002-00487-3: Chip Resistor, 220 Ohm, +/- 5%, 100 mW, -55 to 155 degC, 0402 (1005 Metric), RoHS, Tape and Reel; Manufacturer: Basic Passives; Voltage Rating: 50 V; Case\/Package: 0402; Power Rating: 100 mW; Resistance: 220 Ohm
U14 = CMP-0122128-1: IC LOAD SWITCH 6A 8WSON; Manufacturer: Texas Instruments; SizeZ_mm: 0.8mm; AEC Qualified: No; Max Supply Voltage: 5.7V; Min Supply Voltage: 2.5V; Nominal Supply Current: 20-50uA; Number Of Channels: 1; On State Resistance: 16mΩ; Output Voltage: 0.8-5.7V; Standoff Height: 0mm; TaMax_C: +105°C; TaMin_C: -40°C; TJmax_C: +125°C; Turn Off Delay Time: 9us; Turn On Delay Time: 730us
U22 = CMP-0074067-1: 12.6-V, 7-A Fully-Integrated Synchronous Boost Converters in 2.0-mm x 2.5-mm VQFN Package, RNR0011A (VQFN-HR-11); Alternate PartNumber: TPS61089RNRT; Alternate Manufacturer: Texas Instruments; SizeAreaWB_mm2: 10.5; U/M: EA; SizeZ_mm: 1.0; SizeX_mm: 2.5; SizeY_mm: 2.0; SizeArea_mm2: 5.0; CompType: IC

## Sheet PROC195_PMIC_BUCK.SchDoc
size 431 x 279 mm; Date: Not shown in title block; ApprovedBy: Not shown in title block; CheckedBy: Not shown in title block; Author: Not shown in title block; CompanyName: Not shown in title block; Engineer: Not shown in title block; Organization: Not shown in title block; Address1: Not shown in title block; Address2: Not shown in title block; Address3: Not shown in title block; Address4: Not shown in title block; DocumentNumber: 6; Revision: Use project parameter SCH_Rev; SheetNumber: 8; SheetTotal: 20; PageSetup: Record=PageOptions¦CenterHorizontal=True¦CenterVertical=True¦PrintScale=1.00¦XCorrection=1.00¦YCorrection=1.00¦PrintKind=0¦BorderSize=5000000¦LeftOffset=0¦BottomOffset=0¦Orientation=2¦PaperLength=1000¦PaperWidth=1000¦Scale=100¦PaperSource=15¦PrintQuality=600¦MediaType=1¦DitherType=10¦PaperKind=Letter¦PrintScaleMode=1
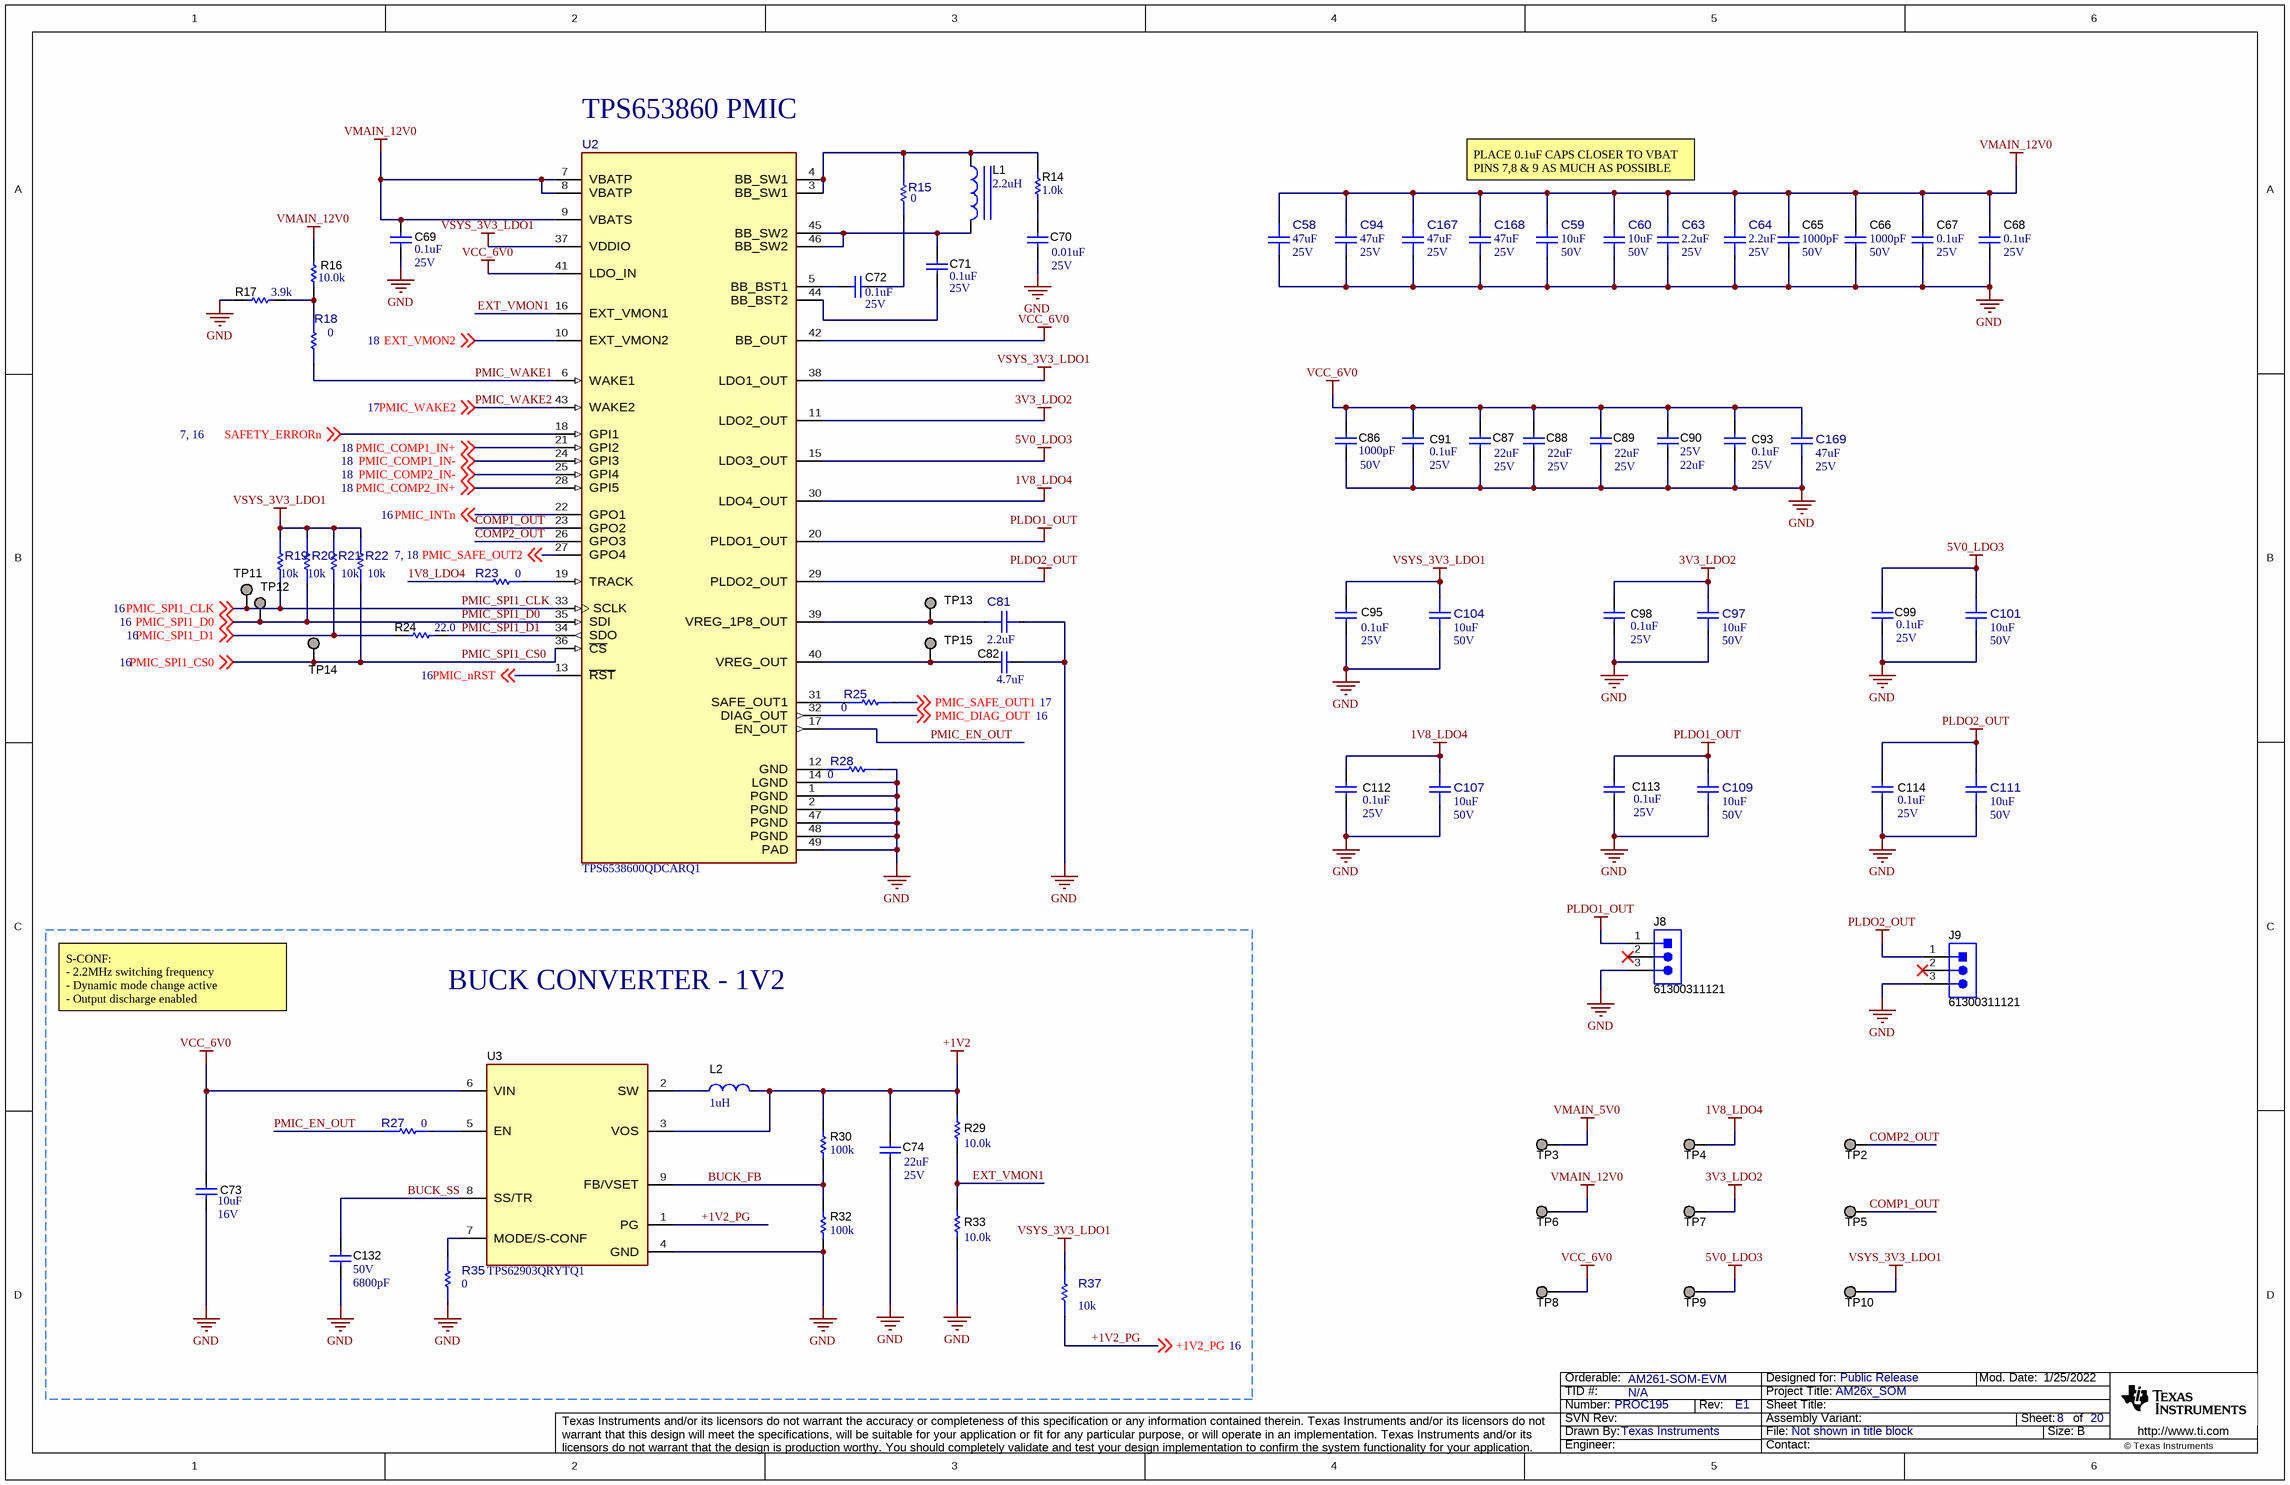
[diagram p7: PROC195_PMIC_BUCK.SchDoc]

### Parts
C58  ValueDisplayed: 47uF  VDC_V: 25V  [FP-GRM31CR61E476ME44K_1206-MFG]  (hidden comment: GRM31CR61E476ME44K)
C59  ValueDisplayed: 10uF  VDC_V: 50V  [FP-GRM21BR61H106KE43L_0805-MFG]  (hidden comment: GRM21BR61H106KE43L)
C60  ValueDisplayed: 10uF  VDC_V: 50V  [FP-GRM21BR61H106KE43L_0805-MFG]  (hidden comment: GRM21BR61H106KE43L)
C63  ValueDisplayed: 2.2uF  VDC_V: 25V  [FP-GRM155R61E225KE11D_0402 (1005 metric)-MFG]  (hidden comment: GRM155R61E225KE11D)
C64  ValueDisplayed: 2.2uF  VDC_V: 25V  [FP-GRM155R61E225KE11D_0402 (1005 metric)-MFG]  (hidden comment: GRM155R61E225KE11D)
C65  Value2: 50V  ValueDisplayed: 1000pF  [0402]  (hidden comment: GRM1555C1H102JA01D)
C66  Value2: 50V  ValueDisplayed: 1000pF  [0402]  (hidden comment: GRM1555C1H102JA01D)
C67  Value2: 25V  ValueDisplayed: 0.1uF  [0402]  (hidden comment: GRM155R71E104KE14D)
C68  Value2: 25V  ValueDisplayed: 0.1uF  [0402]  (hidden comment: GRM155R71E104KE14D)
C69  VDC_V: 25V  ValueDisplayed: 0.1uF  [0402]  (hidden comment: GRM155R71E104KE14D)
C70  Value2: 25V  ValueDisplayed: 0.01uF  [0402]  (hidden comment: GCM155R71E103KA37D)
C71  VDC_V: 25V  ValueDisplayed: 0.1uF  [0402]  (hidden comment: GRM155R71E104KE14D)
C72  VDC_V: 25V  ValueDisplayed: 0.1uF  [0402]  (hidden comment: GRM155R71E104KE14D)
C73  VDC_V: 16V  ValueDisplayed: 10uF  [0603]  (hidden comment: GRM188R61C106MAALD)
C74  VDC_V: 25V  ValueDisplayed: 22uF  [0805_HV]  (hidden comment: GRM21BR61E226ME44L)
C81  ValueDisplayed: 2.2uF  [FP-GRM155R61E225KE11D_0402 (1005 metric)-MFG]  (hidden comment: GRM155R61E225KE11D)
C82  ValueDisplayed: 4.7uF  [0402]  (hidden comment: GRM155R61A475MEAAD)
C86  VDC_V: 50V  ValueDisplayed: 1000pF  [0402]  (hidden comment: GRM1555C1H102JA01D)
C87  VDC_V: 25V  ValueDisplayed: 22uF  [0805_HV]  (hidden comment: GRM21BR61E226ME44L)
C88  VDC_V: 25V  ValueDisplayed: 22uF  [0805_HV]  (hidden comment: GRM21BR61E226ME44L)
C89  VDC_V: 25V  ValueDisplayed: 22uF  [0805_HV]  (hidden comment: GRM21BR61E226ME44L)
C90  VDC_V: 25V  ValueDisplayed: 22uF  [0805_HV]  (hidden comment: GRM21BR61E226ME44L)
C91  VDC_V: 25V  ValueDisplayed: 0.1uF  [0402]  (hidden comment: GRM155R71E104KE14D)
C93  VDC_V: 25V  ValueDisplayed: 0.1uF  [0402]  (hidden comment: GRM155R71E104KE14D)
C94  ValueDisplayed: 47uF  VDC_V: 25V  [FP-GRM31CR61E476ME44K_1206-MFG]  (hidden comment: GRM31CR61E476ME44K)
C95  VDC_V: 25V  ValueDisplayed: 0.1uF  [0402]  (hidden comment: GRM155R71E104KE14D)
C97  ValueDisplayed: 10uF  VDC_V: 50V  [FP-GRM21BR61H106KE43L_0805-MFG]  (hidden comment: GRM21BR61H106KE43L)
C98  VDC_V: 25V  ValueDisplayed: 0.1uF  [0402]  (hidden comment: GRM155R71E104KE14D)
C99  VDC_V: 25V  ValueDisplayed: 0.1uF  [0402]  (hidden comment: GRM155R71E104KE14D)
C101  ValueDisplayed: 10uF  VDC_V: 50V  [FP-GRM21BR61H106KE43L_0805-MFG]  (hidden comment: GRM21BR61H106KE43L)
C104  ValueDisplayed: 10uF  VDC_V: 50V  [FP-GRM21BR61H106KE43L_0805-MFG]  (hidden comment: GRM21BR61H106KE43L)
C107  ValueDisplayed: 10uF  VDC_V: 50V  [FP-GRM21BR61H106KE43L_0805-MFG]  (hidden comment: GRM21BR61H106KE43L)
C109  ValueDisplayed: 10uF  VDC_V: 50V  [FP-GRM21BR61H106KE43L_0805-MFG]  (hidden comment: GRM21BR61H106KE43L)
C111  ValueDisplayed: 10uF  VDC_V: 50V  [FP-GRM21BR61H106KE43L_0805-MFG]  (hidden comment: GRM21BR61H106KE43L)
C112  VDC_V: 25V  ValueDisplayed: 0.1uF  [0402]  (hidden comment: GRM155R71E104KE14D)
C113  VDC_V: 25V  ValueDisplayed: 0.1uF  [0402]  (hidden comment: GRM155R71E104KE14D)
C114  VDC_V: 25V  ValueDisplayed: 0.1uF  [0402]  (hidden comment: GRM155R71E104KE14D)
C132  VDC_V: 50V  ValueDisplayed: 6800pF  [0402]  (hidden comment: GRM155R71H682KA88D)
C167  ValueDisplayed: 47uF  VDC_V: 25V  [FP-GRM31CR61E476ME44K_1206-MFG]  (hidden comment: GRM31CR61E476ME44K)
C168  ValueDisplayed: 47uF  VDC_V: 25V  [FP-GRM31CR61E476ME44K_1206-MFG]  (hidden comment: GRM31CR61E476ME44K)
C169  ValueDisplayed: 47uF  VDC_V: 25V  [FP-GRM31CR61E476ME44K_1206-MFG]  (hidden comment: GRM31CR61E476ME44K)
J8  61300311121  [WURTH_61300311121]
J9  61300311121  [WURTH_61300311121]
L1  ValueDisplayed: 2.2uH  [IHLP-2020BZ]  (hidden comment: IHLP2020BZER2R2M01)
L2  value 1uH  [FP-XGL4030-102MEC_SMD_IND_4MM0_4MM0-MFG]  (hidden comment: XGL4030-102MEC)
R14  ValueDisplayed: 1.0k  [0402]  (hidden comment: ERJ-2GEJ102X)
R15  value 0  [FP-ERJ-2GE0R00X_0402-MFG]  (hidden comment: ERJ-2GE0R00X)
R16  ValueDisplayed: 10.0k  [0402]  (hidden comment: AC0402FR-0710KL)
R17  ValueDisplayed: 3.9k  [0402]  (hidden comment: CRCW04023K90JNED)
R18  value 0  [FP-ERJ-2GE0R00X_0402-MFG]  (hidden comment: ERJ-2GE0R00X)
R19  value 10k  [FP-RC0402JR-0710KL_0402-MFG]  (hidden comment: RC0402JR-0710KL)
R20  value 10k  [FP-RC0402JR-0710KL_0402-MFG]  (hidden comment: RC0402JR-0710KL)
R21  value 10k  [FP-RC0402JR-0710KL_0402-MFG]  (hidden comment: RC0402JR-0710KL)
R22  value 10k  [FP-RC0402JR-0710KL_0402-MFG]  (hidden comment: RC0402JR-0710KL)
R23  value 0  [FP-ERJ-2GE0R00X_0402-MFG]  (hidden comment: ERJ-2GE0R00X)
R24  ValueDisplayed: 22.0  [0201]  (hidden comment: RC0201FR-0722RL)
R25  value 0  [FP-ERJ-2GE0R00X_0402-MFG]  (hidden comment: ERJ-2GE0R00X)
R27  value 0  [FP-ERJ-2GE0R00X_0402-MFG]  (hidden comment: ERJ-2GE0R00X)
R28  value 0  [FP-ERJ-2GE0R00X_0402-MFG]  (hidden comment: ERJ-2GE0R00X)
R29  value 10.0k  [0402]  (hidden comment: AC0402FR-0710KL)
R30  value 100k  [0402]  (hidden comment: CRCW0402100KJNED)
R32  value 100k  [0402]  (hidden comment: CRCW0402100KJNED)
R33  value 10.0k  [0402]  (hidden comment: AC0402FR-0710KL)
R35  value 0  [FP-ERJ-2GE0R00X_0402-MFG]  (hidden comment: ERJ-2GE0R00X)
R37  value 10k  [FP-RC0402JR-0710KL_0402-MFG]  (hidden comment: RC0402JR-0710KL)
TP2  TESTPOINT  [TP_25MIL-SMT]  (value not drawn)  (no BOM)
TP3  TESTPOINT  [TP_25MIL-SMT]  (value not drawn)  (no BOM)
TP4  TESTPOINT  [TP_25MIL-SMT]  (value not drawn)  (no BOM)
TP5  TESTPOINT  [TP_25MIL-SMT]  (value not drawn)  (no BOM)
TP6  TESTPOINT  [TP_25MIL-SMT]  (value not drawn)  (no BOM)
TP7  TESTPOINT  [TP_25MIL-SMT]  (value not drawn)  (no BOM)
TP8  TESTPOINT  [TP_25MIL-SMT]  (value not drawn)  (no BOM)
TP9  TESTPOINT  [TP_25MIL-SMT]  (value not drawn)  (no BOM)
TP10  TESTPOINT  [TP_25MIL-SMT]  (value not drawn)  (no BOM)
TP11  TESTPOINT  [TP_25MIL-SMT]  (value not drawn)  (no BOM)
TP12  TESTPOINT  [TP_25MIL-SMT]  (value not drawn)  (no BOM)
TP13  TESTPOINT  [TP_25MIL-SMT]  (value not drawn)  (no BOM)
TP14  TESTPOINT  [TP_25MIL-SMT]  (value not drawn)  (no BOM)
TP15  TESTPOINT  [TP_25MIL-SMT]  (value not drawn)  (no BOM)
U2  TPS6538600QDCARQ1  [DCA0048J-MFG]
U3  TPS62903QRYTQ1  [RYT0009A-MFG]

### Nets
1V8_LDO4: C107.1 C112.1 R23.1 TP4.1 U2.30(LDO4_OUT)
3V3_LDO2: C97.1 C98.1 TP7.1 U2.11(LDO2_OUT)
5V0_LDO3: C99.1 C101.1 TP9.1 U2.15(LDO3_OUT)
+1V2: C74.1 L2.2 R29.2 R30.2 U3.3(VOS)
GND: C58.2 C59.1 C60.1 C63.2 C64.2 C65.1 C66.1 C67.2 C68.2 C69.2 C70.2 C73.2 C74.2 C81.2 C82.1 C86.2 C87.1 C88.1 C89.1 C90.1 C91.2 C93.2 C94.2 C95.2 C97.2 C98.2 C99.2 C101.2 C104.2 C107.2 C109.2 C111.2 C112.2 C113.2 C114.2 C132.2 C167.2 C168.2 C169.2 J8.3 J9.3 R17.1 R28.2 R32.1 R33.1 R35.1 U2.1(PGND) U2.2(PGND) U2.14(LGND) U2.47(PGND) U2.48(PGND) U2.49(PAD) U3.4(GND)
PLDO1_OUT: C109.1 C113.1 J8.1 U2.20(PLDO1_OUT)
PLDO2_OUT: C111.1 C114.1 J9.1 U2.29(PLDO2_OUT)
VCC_6V0: C73.1 C86.1 C87.2 C88.2 C89.2 C90.2 C91.1 C93.1 C169.1 TP8.1 U2.41(LDO_IN) U2.42(BB_OUT) U3.6(VIN)
VMAIN_5V0: TP3.1
VMAIN_12V0: C58.1 C59.2 C60.2 C63.1 C64.1 C65.2 C66.2 C67.1 C68.1 C69.1 C94.1 C167.1 C168.1 R16.2 TP6.1 U2.7(VBATP) U2.8(VBATP) U2.9(VBATS)
VSYS_3V3_LDO1: C95.1 C104.1 R19.1 R20.1 R21.1 R22.1 R37.2 TP10.1 U2.37(VDDIO) U2.38(LDO1_OUT)
+1V2_PG: R37.1 U3.1(PG) ; off-sheet +1V2_PG
BUCK_FB: R30.1 R32.2 U3.9(FB/VSET)
BUCK_SS: C132.1 U3.8(SS/TR)
COMP1_OUT: TP5.1 U2.23(GPO2)
COMP2_OUT: TP2.1 U2.26(GPO3)
EXT_VMON1: R29.1 R33.2 U2.16(EXT_VMON1)
EXT_VMON2: U2.10(EXT_VMON2) ; off-sheet EXT_VMON2
PMIC_COMP1_IN+: U2.21(GPI2) ; off-sheet PMIC_COMP1_IN+
PMIC_COMP1_IN-: U2.24(GPI3) ; off-sheet PMIC_COMP1_IN-
PMIC_COMP2_IN+: U2.28(GPI5) ; off-sheet PMIC_COMP2_IN+
PMIC_COMP2_IN-: U2.25(GPI4) ; off-sheet PMIC_COMP2_IN-
PMIC_DIAG_OUT: U2.32(DIAG_OUT) ; off-sheet PMIC_DIAG_OUT
PMIC_EN_OUT: R27.1 U2.17(EN_OUT)
PMIC_INTn: U2.22(GPO1) ; off-sheet PMIC_INTn
PMIC_nRST: U2.13(~{RST}) ; off-sheet PMIC_nRST
PMIC_SAFE_OUT1: R25.2 ; off-sheet PMIC_SAFE_OUT1
PMIC_SAFE_OUT2: U2.27(GPO4) ; off-sheet PMIC_SAFE_OUT2
PMIC_SPI1_CLK: R19.2 TP11.1 U2.33(SCLK) ; off-sheet PMIC_SPI1_CLK
PMIC_SPI1_CS0: R22.2 TP14.1 U2.36(~{CS}) ; off-sheet PMIC_SPI1_CS0
PMIC_SPI1_D0: R20.2 TP12.1 U2.35(SDI) ; off-sheet PMIC_SPI1_D0
PMIC_SPI1_D1: R21.2 R24.1 ; off-sheet PMIC_SPI1_D1
PMIC_WAKE2: U2.43(WAKE2) ; off-sheet PMIC_WAKE2
SAFETY_ERRORn: U2.18(GPI1) ; off-sheet SAFETY_ERRORn
NetC70_1: C70.1 R14.2
NetC71_1: C71.1 L1.2 U2.45(BB_SW2) U2.46(BB_SW2)
NetC71_2: C71.2 U2.44(BB_BST2)
NetC72_1: C72.1 R15.2
NetC72_2: C72.2 U2.5(BB_BST1)
NetC81_1: C81.1 TP13.1 U2.39(VREG_1P8_OUT)
NetC82_2: C82.2 TP15.1 U2.40(VREG_OUT)
NetL1_1: L1.1 R14.1 R15.1 U2.3(BB_SW1) U2.4(BB_SW1)
NetL2_1: L2.1 U3.2(SW)
NetR16_1: R16.1 R17.2 R18.2
NetR18_1: R18.1 U2.6(WAKE1)
NetR23_2: R23.2 U2.19(TRACK)
NetR24_2: R24.2 U2.34(SDO)
NetR25_1: R25.1 U2.31(SAFE_OUT1)
NetR27_2: R27.2 U3.5(EN)
NetR28_1: R28.1 U2.12(GND)
NetR35_2: R35.2 U3.7(MODE/S-CONF)

Not connected (* = marked no-connect by the designer): J8 2*; J9 2*

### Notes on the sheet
- TPS653860 PMIC
- PLACE 0.1uF CAPS CLOSER TO VBAT PINS 7,8 & 9 AS MUCH AS POSSIBLE
- (near U2) PMIC_WAKE2
- (near U2) PMIC_WAKE1
- (near R23) PMIC_SPI1_CLK
- PMIC_SPI1_D0
- PMIC_SPI1_D1
- PMIC_SPI1_CS0
- S-CONF:
  - 2.2MHz switching frequency
  - Dynamic mode change active
  - Output discharge enabled
- BUCK CONVERTER - 1V2

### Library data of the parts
C58 C94 C167-C169 = CMP-0122098-1: as C62 on sheet PROC195__FET_BOOST_REG
C59 C60 C97 C101 C104 C107 C109 C111 = CMP-0122097-1: Chip Multilayer Ceramic Capacitors for General Purpose, 0805, 10uF, X5R, 15%, 10%, 50V; Manufacturer: Murata; AEC Qualified: No; Cap_F: 10µF; SizeZ_mm: 1.45mm; Value: 10µF
C63 C64 C81 = CMP-0089929-1: 2.2µF ±10% 25V Ceramic Capacitor X5R 0402 (1005 Metric); Manufacturer: Murata; SizeZ_mm: 0.7mm; AEC Qualified: No; TempCo: 15%
C65 C66 C86 = CMP-0006412-2: as C83 on sheet PROC195__FET_BOOST_REG
C67-C69 C71 C72 C91 C93 C95 C98 C99 C112-C114 = CMP-0006659-2: as C61 on sheet PROC195__FET_BOOST_REG
C70 = CMP-0006352-2: CAP, CERM, 0.01 uF, 25 V, +/- 10%, X7R, 0402; Manufacturer: MuRata; TaMin_C: -55°C; Polarized: N; SizeAreaWB_mm2: 3; Value1: Unknown; U/M: EA; Value: 0.01uF; TaMax_C: 125°C; SizeZ_mm: 0.6; SizeX_mm: 1; SizeY_mm: 0.5; Cap_F: 10nF; AEC Category: Q200
C73 = CMP-0007336-5: CAP, CERM, 10 uF, 16 V, +/- 20%, X5R, 0603; Manufacturer: MuRata; TaMin_C: -55°C; Polarized: N; SizeAreaWB_mm2: 4.68; Value1: Unknown; U/M: EA; Value: 10uF; TaMax_C: 85°C; SizeZ_mm: 1; SizeX_mm: 1.6; SizeY_mm: 0.8; SizeArea_mm2: 1.28; Cap_F: 10µF; AEC Category: Q200
C74 C87-C90 = CMP-0008305-2: as C100 on sheet PROC195__FET_BOOST_REG
C82 = CMP-0006582-2: CAP, CERM, 4.7 uF, 10 V, +/- 20%, X5R, 0402; Manufacturer: MuRata; TaMin_C: -55°C; Polarized: N; SizeAreaWB_mm2: 3; Value1: Unknown; U/M: EA; Value: 4.7uF; TaMax_C: 85°C; SizeZ_mm: 0.6; SizeX_mm: 1; SizeY_mm: 0.5; Value2: 10V; Cap_F: 4.7µF; AEC Category: Q200
C132 = CMP-0006696-2: CAP, CERM, 6800 pF, 50 V, +/- 10%, X7R, 0402; Manufacturer: MuRata; TaMin_C: -55°C; Polarized: N; SizeAreaWB_mm2: 3; Value1: Unknown; U/M: EA; Value: 6800pF; TaMax_C: 125°C; SizeZ_mm: 0.6; SizeX_mm: 1; SizeY_mm: 0.5; Cap_F: 6.8nF; AEC Category: Q200
J8 J9 = CMP-0054796-4: Header, 2.54 mm, 3x1, Gold, TH; Manufacturer: Wurth Elektronik; Green_REACh: Passed; CT: FALSE; CNHeader: TRUE; Green_Lifecycle: Active
L1 = CMP-0063291-1: Inductor, Shielded Drum Core, Powdered Iron, 2.2 uH, 4.2 A, 0.0456 ohm, SMD; Manufacturer: Vishay-Dale; Isat: 12.5A @ 20% inductance drop; Irms: 4.2A @ 40C rise; Green_Lifecycle: Active; SizeAreaWB_mm2: 53.7782; DCR_ohm: 0.0456; Green_REACh: Passed; Value: 2.2uH; Imax_A: 4.2A; SizeZ_mm: 2; SizeX_mm: 5.49; SizeY_mm: 5.18; SizeArea_mm2: 28.4382; Ind_H: 2.2µH; AEC Category: Q200
L2 = CMP-0090842-1: Power Inductor, shielded, composite, 1uH 20% tol, DCR 7.2mOhms, SRF 65MHz, Isat 4.8A, Irms 13A, AEC-Q200; Manufacturer: Coilcraft; TaMin_C: -40°C; TaMax_C: +125°C; Test Frequency: 1MHz; DCR_ohm: 7.2m; AEC Grade: Grade 1; SizeZ_mm: 3.1mm; AEC Qualified: Yes; Shrouded: true; Ind_H: 1µH
R14 = CMP-0078193-1: RES, 1.0 k, 5%, 0.1 W, AEC-Q200 Grade 0, 0402; Manufacturer: Panasonic; Power_W: 100mW; TempCo: 200 ppm/C; Value_Code: 1k00; U/M: EA; Value: 1.0k; EIA_Code: E24; Res_ohm: 1k; SizeX_mm: 1; SizeY_mm: 0.5; SizeZ_mm: 0.6; Value2: 0.1W; AEC Qualified: Y; VDC_V: 50V; AEC Category: Q200; AEC Grade: 0; Green_REACh: Passed; Green_Lifecycle: Active
R15 R23 R25 R28 = CMP-0002710-1: as R45 on sheet PROC195__FET_BOOST_REG
R16 = CMP-0077731-1: RES, 10.0 k, 1%, 0.063 W, AEC-Q200 Grade 0, 0402; Manufacturer: Yageo America; Power_W: 63mW; TempCo: 100 ppm/C; Value_Code: 10k0; U/M: EA; Value: 10.0k; EIA_Code: E96; Res_ohm: 10k; SizeX_mm: 1.0; SizeY_mm: 0.5; SizeZ_mm: 0.6; Value2: 0.063W; AEC Qualified: Y; VDC_V: 50V; AEC Grade: 0; AEC Category: Q200
R17 = CMP-0026920-5: RES, 3.9 k, 5%, 0.063 W, AEC-Q200 Grade 0, 0402; Manufacturer: Vishay-Dale; Power_W: 63mW; TempCo: 200 ppm/C; Value_Code: 3k90; Value: 3.9k; EIA_Code: E24; SizeX_mm: 1; SizeY_mm: 0.5; SizeZ_mm: 0.6; Value2: 0.063W; AEC Qualified: Y; VDC_V: 50V; AEC Category: Q200; AEC Grade: 0
R18 R27 R35 = CMP-0002710-1: 0 Ohms Jumper Chip Resistor 0402 (1005 Metric) Automotive AEC-Q200 Thick Film; Manufacturer: Panasonic; SizeZ_mm: 0.4mm; AEC Qualified: Yes; AEC Grade: Grade 0; Power: 100mW
R19-R22 = CMP-0094798-1: Res Thick Film 0402 10K Ohm 5% 0.063W(1/16W) ±100ppm/C Pad SMD T/R; Manufacturer: YAGEO; AEC Qualified: No; Category Cd01000Bfc2916C6: Single Components; SizeZ_mm: 0.4mm; VDC_V: 50V; Category 5C6A91606D4187Ad: Resistors; TempCo: 100ppm/°C; Power_W: 63mW; Category 7542B8484461Ae85: Passive Components
R24 = CMP-0027500-1: RES, 22.0, 1%, 0.05 W, 0201; Manufacturer: Yageo America; Power_W: 50mW; TempCo: 200 ppm/C; Value_Code: 22R0; U/M: EA; Value: 22.0; Res_ohm: 22; SizeX_mm: 0.6; SizeY_mm: 0.3; SizeZ_mm: 0.26; Value2: 0.05W; SizeArea_mm2: 0.18; AEC Qualified: N; VDC_V: 25V; AEC Category: Q200
R29 R33 = CMP-0077731-1: RES, 10.0 k, 1%, 0.063 W, AEC-Q200 Grade 0, 0402; Manufacturer: Yageo America; Power_W: 63mW; TempCo: 100 ppm/C; Value_Code: 10k0; U/M: EA; EIA_Code: E96; Res_ohm: 10k; SizeX_mm: 1.0; SizeY_mm: 0.5; SizeZ_mm: 0.6; Value2: 0.063W; AEC Qualified: Y; VDC_V: 50V; AEC Grade: 0; AEC Category: Q200
R30 R32 = CMP-0026823-3: RES, 100 k, 5%, 0.063 W, AEC-Q200 Grade 0, 0402; Manufacturer: Vishay-Dale; Power_W: 63mW; TempCo: 200 ppm/C; EIA_Code: E24; SizeX_mm: 1; SizeY_mm: 0.5; SizeZ_mm: 0.6; Value2: 0.063W; AEC Qualified: Y; VDC_V: 50V; AEC Category: Q200; AEC Grade: 0
R37 = CMP-0094798-1: as R42 on sheet PROC195__FET_BOOST_REG
TP2-TP15 = CMP-0078143-3: TEST POINT.  No entry in BOM.
U2 = CMP-0095884-1: Power Management IC For Safety-Relevant Applications HTSSOP48 5 Outputs 4 LDO and 1 Synchronous Buck-Boost Regulator; Manufacturer: Texas Instruments; SizeZ_mm: 1.2mm; AEC Qualified: Yes; Standoff Height: 0.05mm; Max Supply Voltage: 28V; TaMin_C: -40°C; AEC Grade: Grade 1; TJmax_C: +150°C; Min Supply Voltage: 2.3V; Number Of Outputs: 7; TaMax_C: +125°C
U3 = CMP-0093448-1: 3-V to 18-V, High Efficiency and Low IQ Buck Converter in QFN HR  Package with 165C Junction temperature; Manufacturer: Texas Instruments; SizeZ_mm: 1.05mm; Min Supply Voltage: 3V; Output Type: AdjustableProgrammable; Switching Frequency: 1/2.5MHz; Max Supply Voltage: 18V; Output Voltage: 0.4-5.5V; Number Of Outputs: 1; TJmax_C: +165°C; Standoff Height: 0mm; Nominal Supply Current: 8mA; AEC Qualified: Yes; AEC Grade: Grade 1; Max Duty Cycle: 100%

## Sheet PROC195_MCU_POWER_CAPS.SchDoc
size 431 x 279 mm; Date: Not shown in title block; ApprovedBy: Not shown in title block; CheckedBy: Not shown in title block; Author: Not shown in title block; CompanyName: Not shown in title block; Engineer: Not shown in title block; Organization: Not shown in title block; Address1: Not shown in title block; Address2: Not shown in title block; Address3: Not shown in title block; Address4: Not shown in title block; DocumentNumber: 8; Revision: Use project parameter SCH_Rev; SheetNumber: 9; SheetTotal: 20; PageSetup: Record=PageOptions¦CenterHorizontal=True¦CenterVertical=True¦PrintScale=1.00¦XCorrection=1.00¦YCorrection=1.00¦PrintKind=0¦BorderSize=5000000¦LeftOffset=0¦BottomOffset=0¦Orientation=2¦PaperLength=1000¦PaperWidth=1000¦Scale=100¦PaperSource=15¦PrintQuality=600¦MediaType=1¦DitherType=10¦PaperKind=Letter¦PrintScaleMode=1
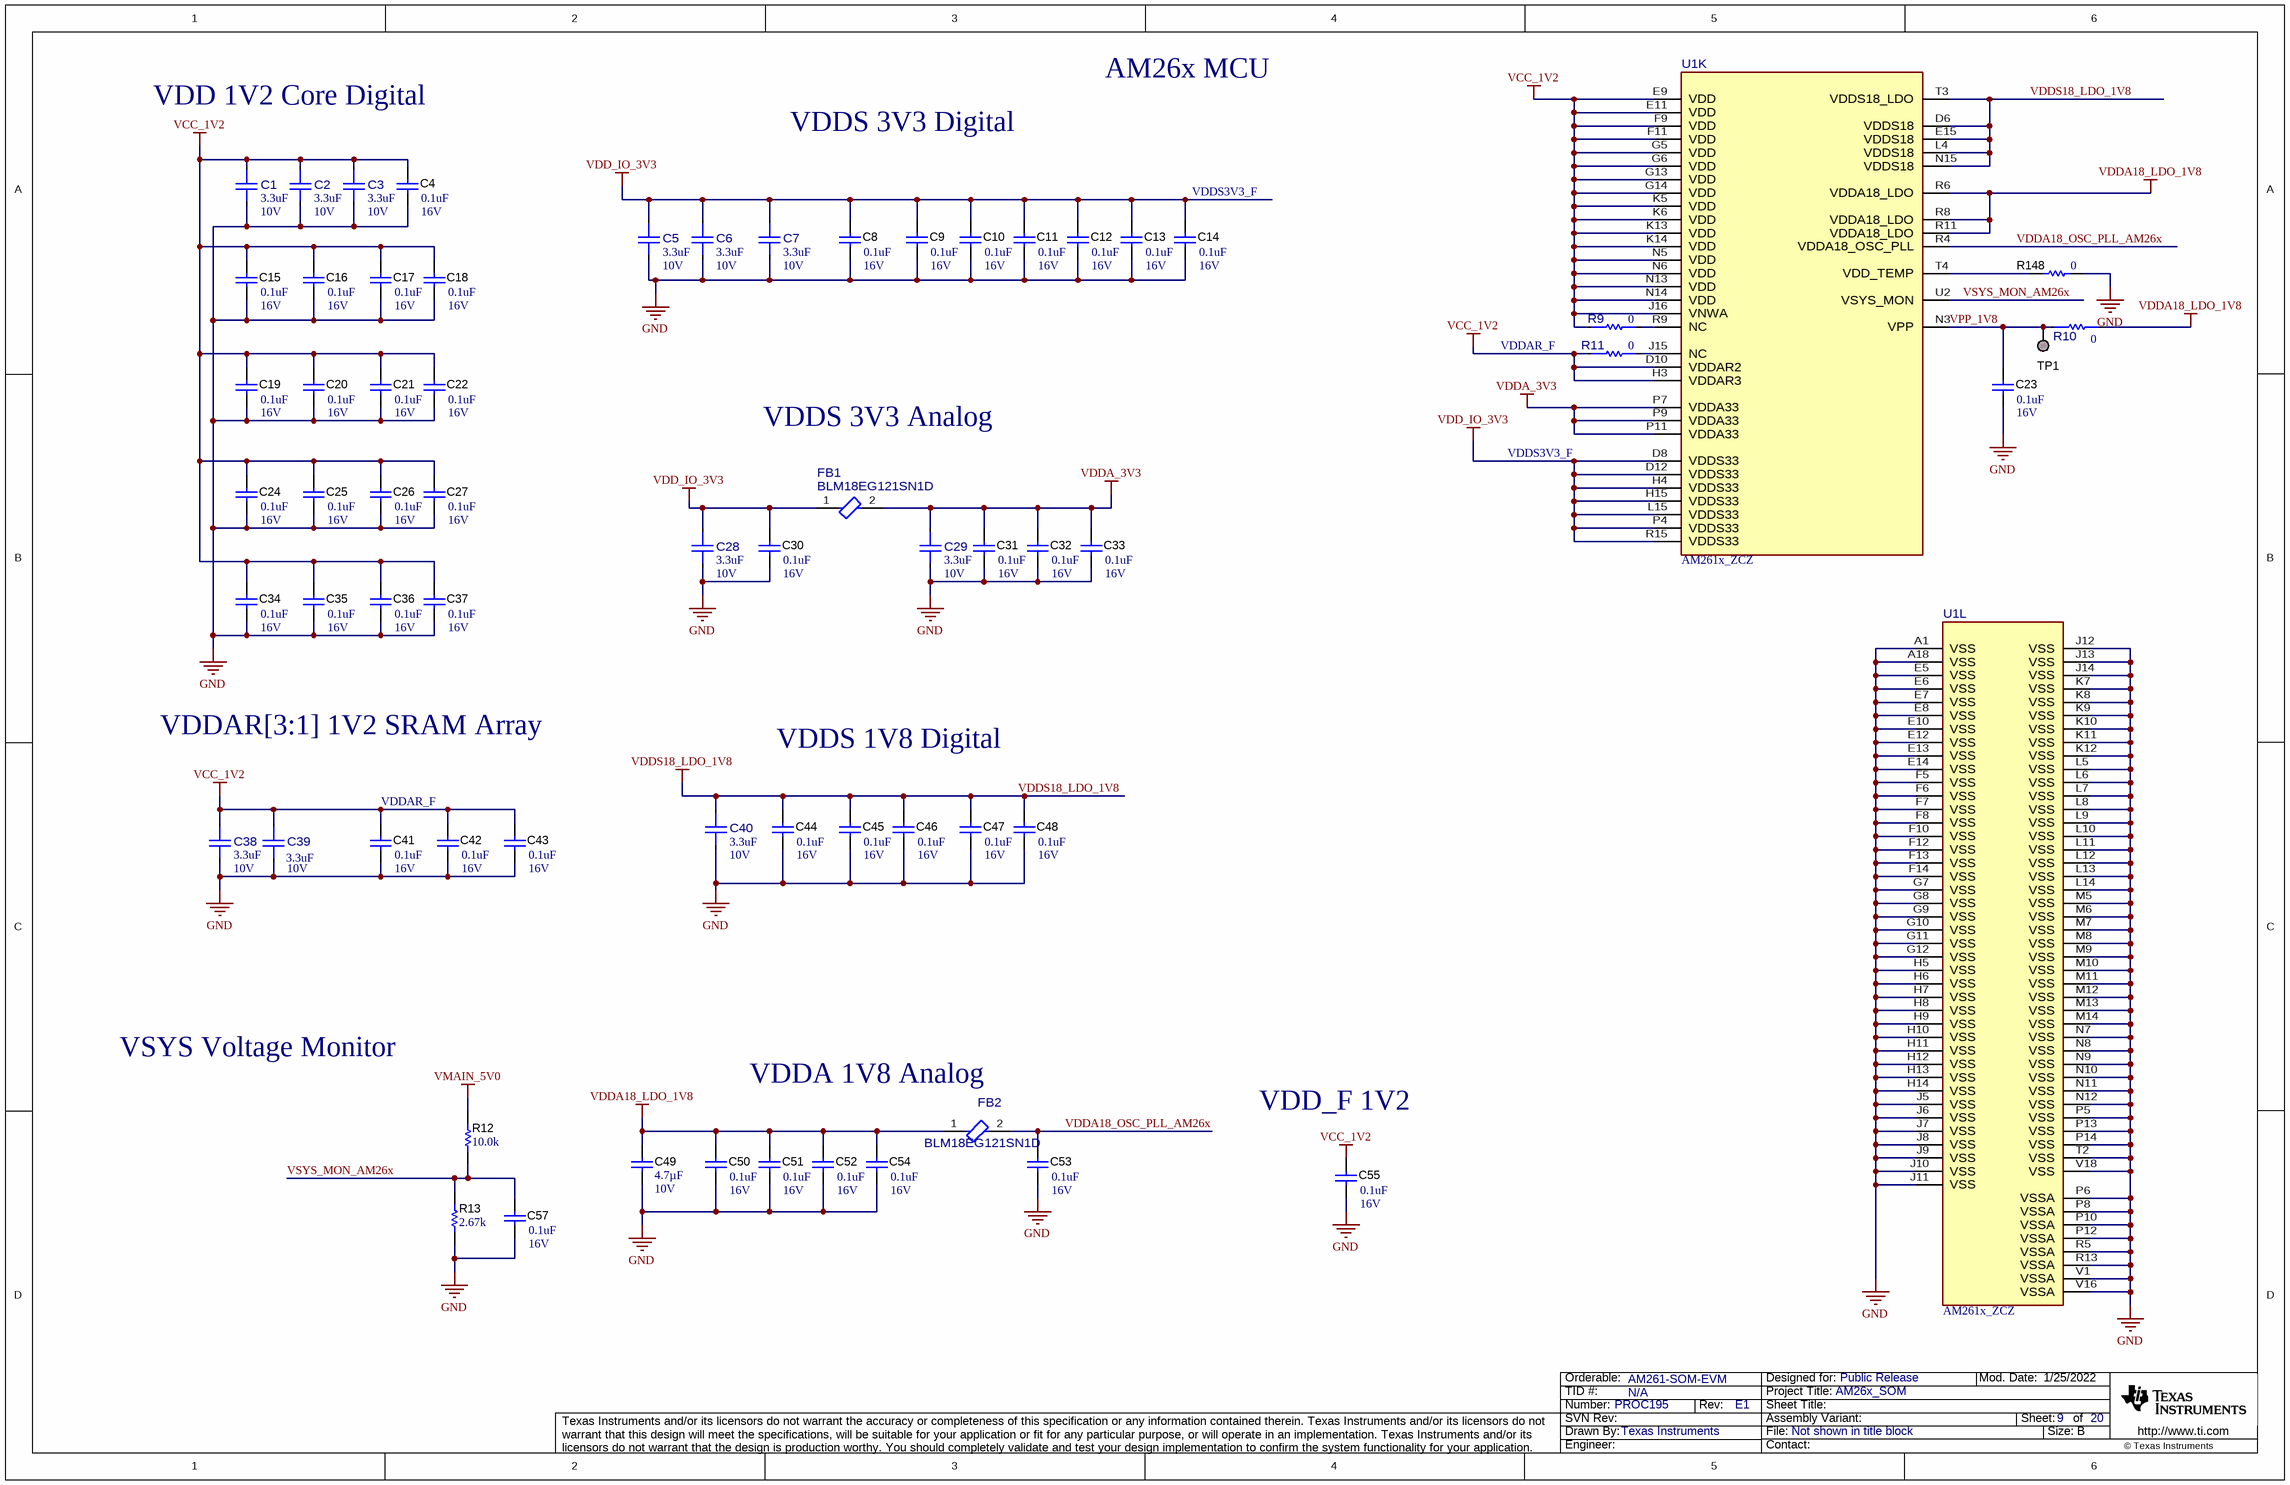
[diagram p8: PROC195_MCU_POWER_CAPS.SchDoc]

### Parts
C1  ValueDisplayed: 3.3uF  VDC_V: 10V  [FP-CL10A335KP8NNNC_0603-MFG]  (hidden comment: CL10A335KP8NNNC)
C2  ValueDisplayed: 3.3uF  VDC_V: 10V  [FP-CL10A335KP8NNNC_0603-MFG]  (hidden comment: CL10A335KP8NNNC)
C3  ValueDisplayed: 3.3uF  VDC_V: 10V  [FP-CL10A335KP8NNNC_0603-MFG]  (hidden comment: CL10A335KP8NNNC)
C4  VDC_V: 16V  ValueDisplayed: 0.1uF  [0201L]  (hidden comment: GRM033Z71C104KE14D)
C5  ValueDisplayed: 3.3uF  VDC_V: 10V  [FP-CL10A335KP8NNNC_0603-MFG]  (hidden comment: CL10A335KP8NNNC)
C6  ValueDisplayed: 3.3uF  VDC_V: 10V  [FP-CL10A335KP8NNNC_0603-MFG]  (hidden comment: CL10A335KP8NNNC)
C7  ValueDisplayed: 3.3uF  VDC_V: 10V  [FP-CL10A335KP8NNNC_0603-MFG]  (hidden comment: CL10A335KP8NNNC)
C8  VDC_V: 16V  ValueDisplayed: 0.1uF  [0201L]  (hidden comment: GRM033Z71C104KE14D)
C9  VDC_V: 16V  ValueDisplayed: 0.1uF  [0201L]  (hidden comment: GRM033Z71C104KE14D)
C10  VDC_V: 16V  ValueDisplayed: 0.1uF  [0201L]  (hidden comment: GRM033Z71C104KE14D)
C11  VDC_V: 16V  ValueDisplayed: 0.1uF  [0201L]  (hidden comment: GRM033Z71C104KE14D)
C12  VDC_V: 16V  ValueDisplayed: 0.1uF  [0201L]  (hidden comment: GRM033Z71C104KE14D)
C13  VDC_V: 16V  ValueDisplayed: 0.1uF  [0201L]  (hidden comment: GRM033Z71C104KE14D)
C14  VDC_V: 16V  ValueDisplayed: 0.1uF  [0201L]  (hidden comment: GRM033Z71C104KE14D)
C15  VDC_V: 16V  ValueDisplayed: 0.1uF  [0201L]  (hidden comment: GRM033Z71C104KE14D)
C16  VDC_V: 16V  ValueDisplayed: 0.1uF  [0201L]  (hidden comment: GRM033Z71C104KE14D)
C17  VDC_V: 16V  ValueDisplayed: 0.1uF  [0201L]  (hidden comment: GRM033Z71C104KE14D)
C18  VDC_V: 16V  ValueDisplayed: 0.1uF  [0201L]  (hidden comment: GRM033Z71C104KE14D)
C19  VDC_V: 16V  ValueDisplayed: 0.1uF  [0201L]  (hidden comment: GRM033Z71C104KE14D)
C20  VDC_V: 16V  ValueDisplayed: 0.1uF  [0201L]  (hidden comment: GRM033Z71C104KE14D)
C21  VDC_V: 16V  ValueDisplayed: 0.1uF  [0201L]  (hidden comment: GRM033Z71C104KE14D)
C22  VDC_V: 16V  ValueDisplayed: 0.1uF  [0201L]  (hidden comment: GRM033Z71C104KE14D)
C23  VDC_V: 16V  ValueDisplayed: 0.1uF  [0201L]  (hidden comment: GRM033Z71C104KE14D)
C24  VDC_V: 16V  ValueDisplayed: 0.1uF  [0201L]  (hidden comment: GRM033Z71C104KE14D)
C25  VDC_V: 16V  ValueDisplayed: 0.1uF  [0201L]  (hidden comment: GRM033Z71C104KE14D)
C26  VDC_V: 16V  ValueDisplayed: 0.1uF  [0201L]  (hidden comment: GRM033Z71C104KE14D)
C27  VDC_V: 16V  ValueDisplayed: 0.1uF  [0201L]  (hidden comment: GRM033Z71C104KE14D)
C28  ValueDisplayed: 3.3uF  VDC_V: 10V  [FP-CL10A335KP8NNNC_0603-MFG]  (hidden comment: CL10A335KP8NNNC)
C29  ValueDisplayed: 3.3uF  VDC_V: 10V  [FP-CL10A335KP8NNNC_0603-MFG]  (hidden comment: CL10A335KP8NNNC)
C30  VDC_V: 16V  ValueDisplayed: 0.1uF  [0201L]  (hidden comment: GRM033Z71C104KE14D)
C31  VDC_V: 16V  ValueDisplayed: 0.1uF  [0201L]  (hidden comment: GRM033Z71C104KE14D)
C32  VDC_V: 16V  ValueDisplayed: 0.1uF  [0201L]  (hidden comment: GRM033Z71C104KE14D)
C33  VDC_V: 16V  ValueDisplayed: 0.1uF  [0201L]  (hidden comment: GRM033Z71C104KE14D)
C34  VDC_V: 16V  ValueDisplayed: 0.1uF  [0201L]  (hidden comment: GRM033Z71C104KE14D)
C35  VDC_V: 16V  ValueDisplayed: 0.1uF  [0201L]  (hidden comment: GRM033Z71C104KE14D)
C36  VDC_V: 16V  ValueDisplayed: 0.1uF  [0201L]  (hidden comment: GRM033Z71C104KE14D)
C37  VDC_V: 16V  ValueDisplayed: 0.1uF  [0201L]  (hidden comment: GRM033Z71C104KE14D)
C38  VDC_V: 10V  ValueDisplayed: 3.3uF  [FP-CL10A335KP8NNNC_0603-MFG]  (hidden comment: CL10A335KP8NNNC)
C39  VDC_V: 10V  ValueDisplayed: 3.3uF  [FP-CL10A335KP8NNNC_0603-MFG]  (hidden comment: CL10A335KP8NNNC)
C40  ValueDisplayed: 3.3uF  VDC_V: 10V  [FP-CL10A335KP8NNNC_0603-MFG]  (hidden comment: CL10A335KP8NNNC)
C41  VDC_V: 16V  ValueDisplayed: 0.1uF  [0201L]  (hidden comment: GRM033Z71C104KE14D)
C42  VDC_V: 16V  ValueDisplayed: 0.1uF  [0201L]  (hidden comment: GRM033Z71C104KE14D)
C43  VDC_V: 16V  ValueDisplayed: 0.1uF  [0201L]  (hidden comment: GRM033Z71C104KE14D)
C44  VDC_V: 16V  ValueDisplayed: 0.1uF  [0201L]  (hidden comment: GRM033Z71C104KE14D)
C45  VDC_V: 16V  ValueDisplayed: 0.1uF  [0201L]  (hidden comment: GRM033Z71C104KE14D)
C46  VDC_V: 16V  ValueDisplayed: 0.1uF  [0201L]  (hidden comment: GRM033Z71C104KE14D)
C47  VDC_V: 16V  ValueDisplayed: 0.1uF  [0201L]  (hidden comment: GRM033Z71C104KE14D)
C48  VDC_V: 16V  ValueDisplayed: 0.1uF  [0201L]  (hidden comment: GRM033Z71C104KE14D)
C49  Cap_F: 4.7µF  VDC_V: 10V  [0402L]  (hidden comment: GRM155R61A475MEAAD)
C50  VDC_V: 16V  ValueDisplayed: 0.1uF  [0201L]  (hidden comment: GRM033Z71C104KE14D)
C51  VDC_V: 16V  ValueDisplayed: 0.1uF  [0201L]  (hidden comment: GRM033Z71C104KE14D)
C52  VDC_V: 16V  ValueDisplayed: 0.1uF  [0201L]  (hidden comment: GRM033Z71C104KE14D)
C53  VDC_V: 16V  ValueDisplayed: 0.1uF  [0201L]  (hidden comment: GRM033Z71C104KE14D)
C54  VDC_V: 16V  ValueDisplayed: 0.1uF  [0201L]  (hidden comment: GRM033Z71C104KE14D)
C55  VDC_V: 16V  ValueDisplayed: 0.1uF  [0201L]  (hidden comment: GRM033Z71C104KE14D)
C57  VDC_V: 16V  ValueDisplayed: 0.1uF  [0201L]  (hidden comment: GRM033Z71C104KE14D)
FB1  BLM18EG121SN1D  [FP-BLM18EG121SN1D_0603-MFG]
FB2  BLM18EG121SN1D  [FP-BLM18EG121SN1D_0603-MFG]
R9  value 0  [FP-ERJ-2GE0R00X_0402-MFG]  (hidden comment: ERJ-2GE0R00X)
R10  value 0  [FP-ERJ-2GE0R00X_0402-MFG]  (hidden comment: ERJ-2GE0R00X)
R11  value 0  [FP-ERJ-2GE0R00X_0402-MFG]  (hidden comment: ERJ-2GE0R00X)
R12  ValueDisplayed: 10.0k  [0402]  (hidden comment: AC0402FR-0710KL)
R13  ValueDisplayed: 2.67k  [0402]  (hidden comment: CRCW04022K67FKED)
R148  ValueDisplayed: 0  [0201]  (hidden comment: ERJ-1GN0R00C)
TP1  TESTPOINT  [TP_25MIL-SMT]  (value not drawn)  (no BOM)
U1  AM261x_ZCZ  [ZCZ0324A-MFG]  (parts K,L of 13)

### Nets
GND: C1.2 C2.2 C3.2 C4.2 C5.2 C6.2 C7.2 C8.2 C9.2 C10.2 C11.2 C12.2 C13.2 C14.2 C15.2 C16.2 C17.2 C18.2 C19.2 C20.2 C21.2 C22.2 C23.2 C24.2 C25.2 C26.2 C27.2 C28.2 C29.2 C30.2 C31.2 C32.2 C33.2 C34.2 C35.2 C36.2 C37.2 C38.2 C39.2 C40.2 C41.2 C42.2 C43.2 C44.2 C45.2 C46.2 C47.2 C48.2 C49.2 C50.2 C51.2 C52.2 C53.2 C54.2 C55.2 C57.2 R13.1 R148.2 U1.A1(VSS) U1.A18(VSS) U1.E5(VSS) U1.E6(VSS) U1.E7(VSS) U1.E8(VSS) U1.E10(VSS) U1.E12(VSS) U1.E13(VSS) U1.E14(VSS) U1.F5(VSS) U1.F6(VSS) U1.F7(VSS) U1.F8(VSS) U1.F10(VSS) U1.F12(VSS) U1.F13(VSS) U1.F14(VSS) U1.G7(VSS) U1.G8(VSS) U1.G9(VSS) U1.G10(VSS) U1.G11(VSS) U1.G12(VSS) U1.H5(VSS) U1.H6(VSS) U1.H7(VSS) U1.H8(VSS) U1.H9(VSS) U1.H10(VSS) U1.H11(VSS) U1.H12(VSS) U1.H13(VSS) U1.H14(VSS) U1.J5(VSS) U1.J6(VSS) U1.J7(VSS) U1.J8(VSS) U1.J9(VSS) U1.J10(VSS) U1.J11(VSS) U1.J12(VSS) U1.J13(VSS) U1.J14(VSS) U1.K7(VSS) U1.K8(VSS) U1.K9(VSS) U1.K10(VSS) U1.K11(VSS) U1.K12(VSS) U1.L5(VSS) U1.L6(VSS) U1.L7(VSS) U1.L8(VSS) U1.L9(VSS) U1.L10(VSS) U1.L11(VSS) U1.L12(VSS) U1.L13(VSS) U1.L14(VSS) U1.M5(VSS) U1.M6(VSS) U1.M7(VSS) U1.M8(VSS) U1.M9(VSS) U1.M10(VSS) U1.M11(VSS) U1.M12(VSS) U1.M13(VSS) U1.M14(VSS) U1.N7(VSS) U1.N8(VSS) U1.N9(VSS) U1.N10(VSS) U1.N11(VSS) U1.N12(VSS) U1.P5(VSS) U1.P6(VSSA) U1.P8(VSSA) U1.P10(VSSA) U1.P12(VSSA) U1.P13(VSS) U1.P14(VSS) U1.R5(VSSA) U1.R13(VSSA) U1.T2(VSS) U1.V1(VSSA) U1.V16(VSSA) U1.V18(VSS)
VCC_1V2: C1.1 C2.1 C3.1 C4.1 C15.1 C16.1 C17.1 C18.1 C19.1 C20.1 C21.1 C22.1 C24.1 C25.1 C26.1 C27.1 C34.1 C35.1 C36.1 C37.1 C38.1 C39.1 C41.1 C42.1 C43.1 C55.1 R9.1 R11.1 U1.D10(VDDAR2) U1.E9(VDD) U1.E11(VDD) U1.F9(VDD) U1.F11(VDD) U1.G5(VDD) U1.G6(VDD) U1.G13(VDD) U1.G14(VDD) U1.H3(VDDAR3) U1.J16(VNWA) U1.K5(VDD) U1.K6(VDD) U1.K13(VDD) U1.K14(VDD) U1.N5(VDD) U1.N6(VDD) U1.N13(VDD) U1.N14(VDD)
VDD_IO_3V3: C5.1 C6.1 C7.1 C8.1 C9.1 C10.1 C11.1 C12.1 C13.1 C14.1 C28.1 C30.1 FB1.1 U1.D8(VDDS33) U1.D12(VDDS33) U1.H4(VDDS33) U1.H15(VDDS33) U1.L15(VDDS33) U1.P4(VDDS33) U1.R15(VDDS33)
VDDA18_LDO_1V8: C49.1 C50.1 C51.1 C52.1 C54.1 FB2.1 R10.2 U1.R6(VDDA18_LDO) U1.R8(VDDA18_LDO) U1.R11(VDDA18_LDO)
VDDA_3V3: C29.1 C31.1 C32.1 C33.1 FB1.2 U1.P7(VDDA33) U1.P9(VDDA33) U1.P11(VDDA33)
VDDS18_LDO_1V8: C40.1 C44.1 C45.1 C46.1 C47.1 C48.1 U1.D6(VDDS18) U1.E15(VDDS18) U1.L4(VDDS18) U1.N15(VDDS18) U1.T3(VDDS18_LDO)
VMAIN_5V0: R12.2
VDDA18_OSC_PLL_AM26x: C53.1 FB2.2 U1.R4(VDDA18_OSC_PLL)
VPP_1V8: C23.1 R10.1 TP1.1 U1.N3(VPP)
VSYS_MON_AM26x: C57.1 R12.1 R13.2 U1.U2(VSYS_MON)
NetR9_2: R9.2 U1.R9(NC)
NetR11_2: R11.2 U1.J15(NC)
NetR148_1: R148.1 U1.T4(VDD_TEMP)

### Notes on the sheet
- AM26x MCU
- VDD 1V2 Core Digital
- VDDS 3V3 Digital
- (near C14) VDDS3V3_F
- VDDAR_F
- VDDS 3V3 Analog
- VDDS3V3_F
- VDDAR[3:1] 1V2 SRAM Array
- VDDS 1V8 Digital
- VSYS Voltage Monitor
- (near FB2) VDDA 1V8 Analog
- VDD_F 1V2

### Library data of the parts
C1-C3 C5-C7 C28 C29 C40 = CMP-0042976-1: Cap Ceramic 3.3uF 10V X5R ±10% Pad SMD 0603 +85°C T/R; Manufacturer: Samsung; AEC Qualified: No; Cap_F: 3.3µF; SizeZ_mm: 0.9mm; TempCo: 15%; Value: 3.3µF
C4 C8-C27 C30-C37 C41-C48 C50-C55 C57 = CMP-0064970-1: CAP, CERM, 0.1 uF, 16 V,+/- 10%, X7R, 0201; Manufacturer: MuRata; TaMin_C: -55°C; Polarized: N; SizeAreaWB_mm2: 2.08; Value1: Unknown; U/M: EA; Value: 0.1uF; TaMax_C: 125°C; SizeZ_mm: 0.26; SizeX_mm: 0.6; SizeY_mm: 0.3; Cap_Case: 0201; SizeArea_mm2: 0.18; Cap_F: 100nF; AEC Category: Q200
C38 C39 = CMP-0042976-1: Cap Ceramic 3.3uF 10V X5R ±10% Pad SMD 0603 +85°C T/R; Manufacturer: Samsung; TempCo: 15%; Value: 3.3µF; SizeZ_mm: 0.9mm; AEC Qualified: No
C49 = CMP-0006582-2: CAP, CERM, 4.7 uF, 10 V, +/- 20%, X5R, 0402; Manufacturer: MuRata; TaMin_C: -55°C; Polarized: N; SizeAreaWB_mm2: 3; Value1: Unknown; U/M: EA; Value: 4.7uF; TaMax_C: 85°C; SizeZ_mm: 0.6; SizeX_mm: 1; SizeY_mm: 0.5; Cap_Case: 0402; AEC Category: Q200
FB1 FB2 = CMP-0089199-1: 120 Ohms @ 100MHz 1  Ferrite Bead 0603 (1608 Metric) 2A 40mOhm; Manufacturer: Murata; DCR_ohm: 60m; AEC Qualified: No; Tolerance_%: 25%; SizeZ_mm: 0.95mm; Impedance At Frequency: 120Ω @ 100MHz
R9 R11 = CMP-0002710-1: as R18 on sheet PROC195_PMIC_BUCK
R10 = CMP-0002710-1: as R45 on sheet PROC195__FET_BOOST_REG
R12 = CMP-0077731-1: RES, 10.0 k, 1%, 0.063 W, AEC-Q200 Grade 0, 0402; Manufacturer: Yageo America; Power_W: 63mW; TempCo: 100 ppm/C; Value_Code: 10k0; U/M: EA; Value: 10.0k; EIA_Code: E96; Res_ohm: 10k; SizeX_mm: 1.0; SizeY_mm: 0.5; SizeZ_mm: 0.6; Value2: 0.063W; AEC Qualified: Y; VDC_V: 50V; AEC Category: Q200; AEC Grade: 0
R13 = CMP-0026240-2: RES, 2.67 k, 1%, 0.063 W, AEC-Q200 Grade 0, 0402; Manufacturer: Vishay-Dale; Power_W: 63mW; TempCo: 100 ppm/C; Value_Code: 2k67; Value: 2.67k; EIA_Code: E96; SizeX_mm: 1; SizeY_mm: 0.5; SizeZ_mm: 0.6; Value2: 0.063W; AEC Qualified: Y; VDC_V: 50V; AEC Category: Q200; AEC Grade: 0
R148 = CMP-0065361-1: RES, 0, 5%, .05 W, AEC-Q200 Grade 0, 0201; Manufacturer: Panasonic; Power_W: 50mW; Green_Lifecycle: Not Set; TempCo: ppm/C; Value_Code: 0000; Green_REACh: Incomplete; U/M: EA; Value: 0; EIA_Code: E24; SizeX_mm: 0.6; SizeY_mm: 0.3; SizeZ_mm: 0.26; Value2: .05W; SizeArea_mm2: 0.18; AEC Qualified: Y; AEC Category: Q200
TP1 = CMP-0078143-3: TEST POINT.  No entry in BOM.
U1 = CMP-0121930-1: Manufacturer: Texas Instruments; SizeZ_mm: 1.4mm; Standoff Height: 0.35mm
